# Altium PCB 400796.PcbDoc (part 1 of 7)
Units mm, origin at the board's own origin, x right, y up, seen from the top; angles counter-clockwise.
Board outline 53 x 53 mm, 6 copper layers (Top Layer, Mid Layer 1, Mid Layer 2, Mid Layer 3, Mid Layer 4, Bottom Layer), stack 1.494 mm thick; 319 components, 236 nets, 1249 pads, 2569 vias.
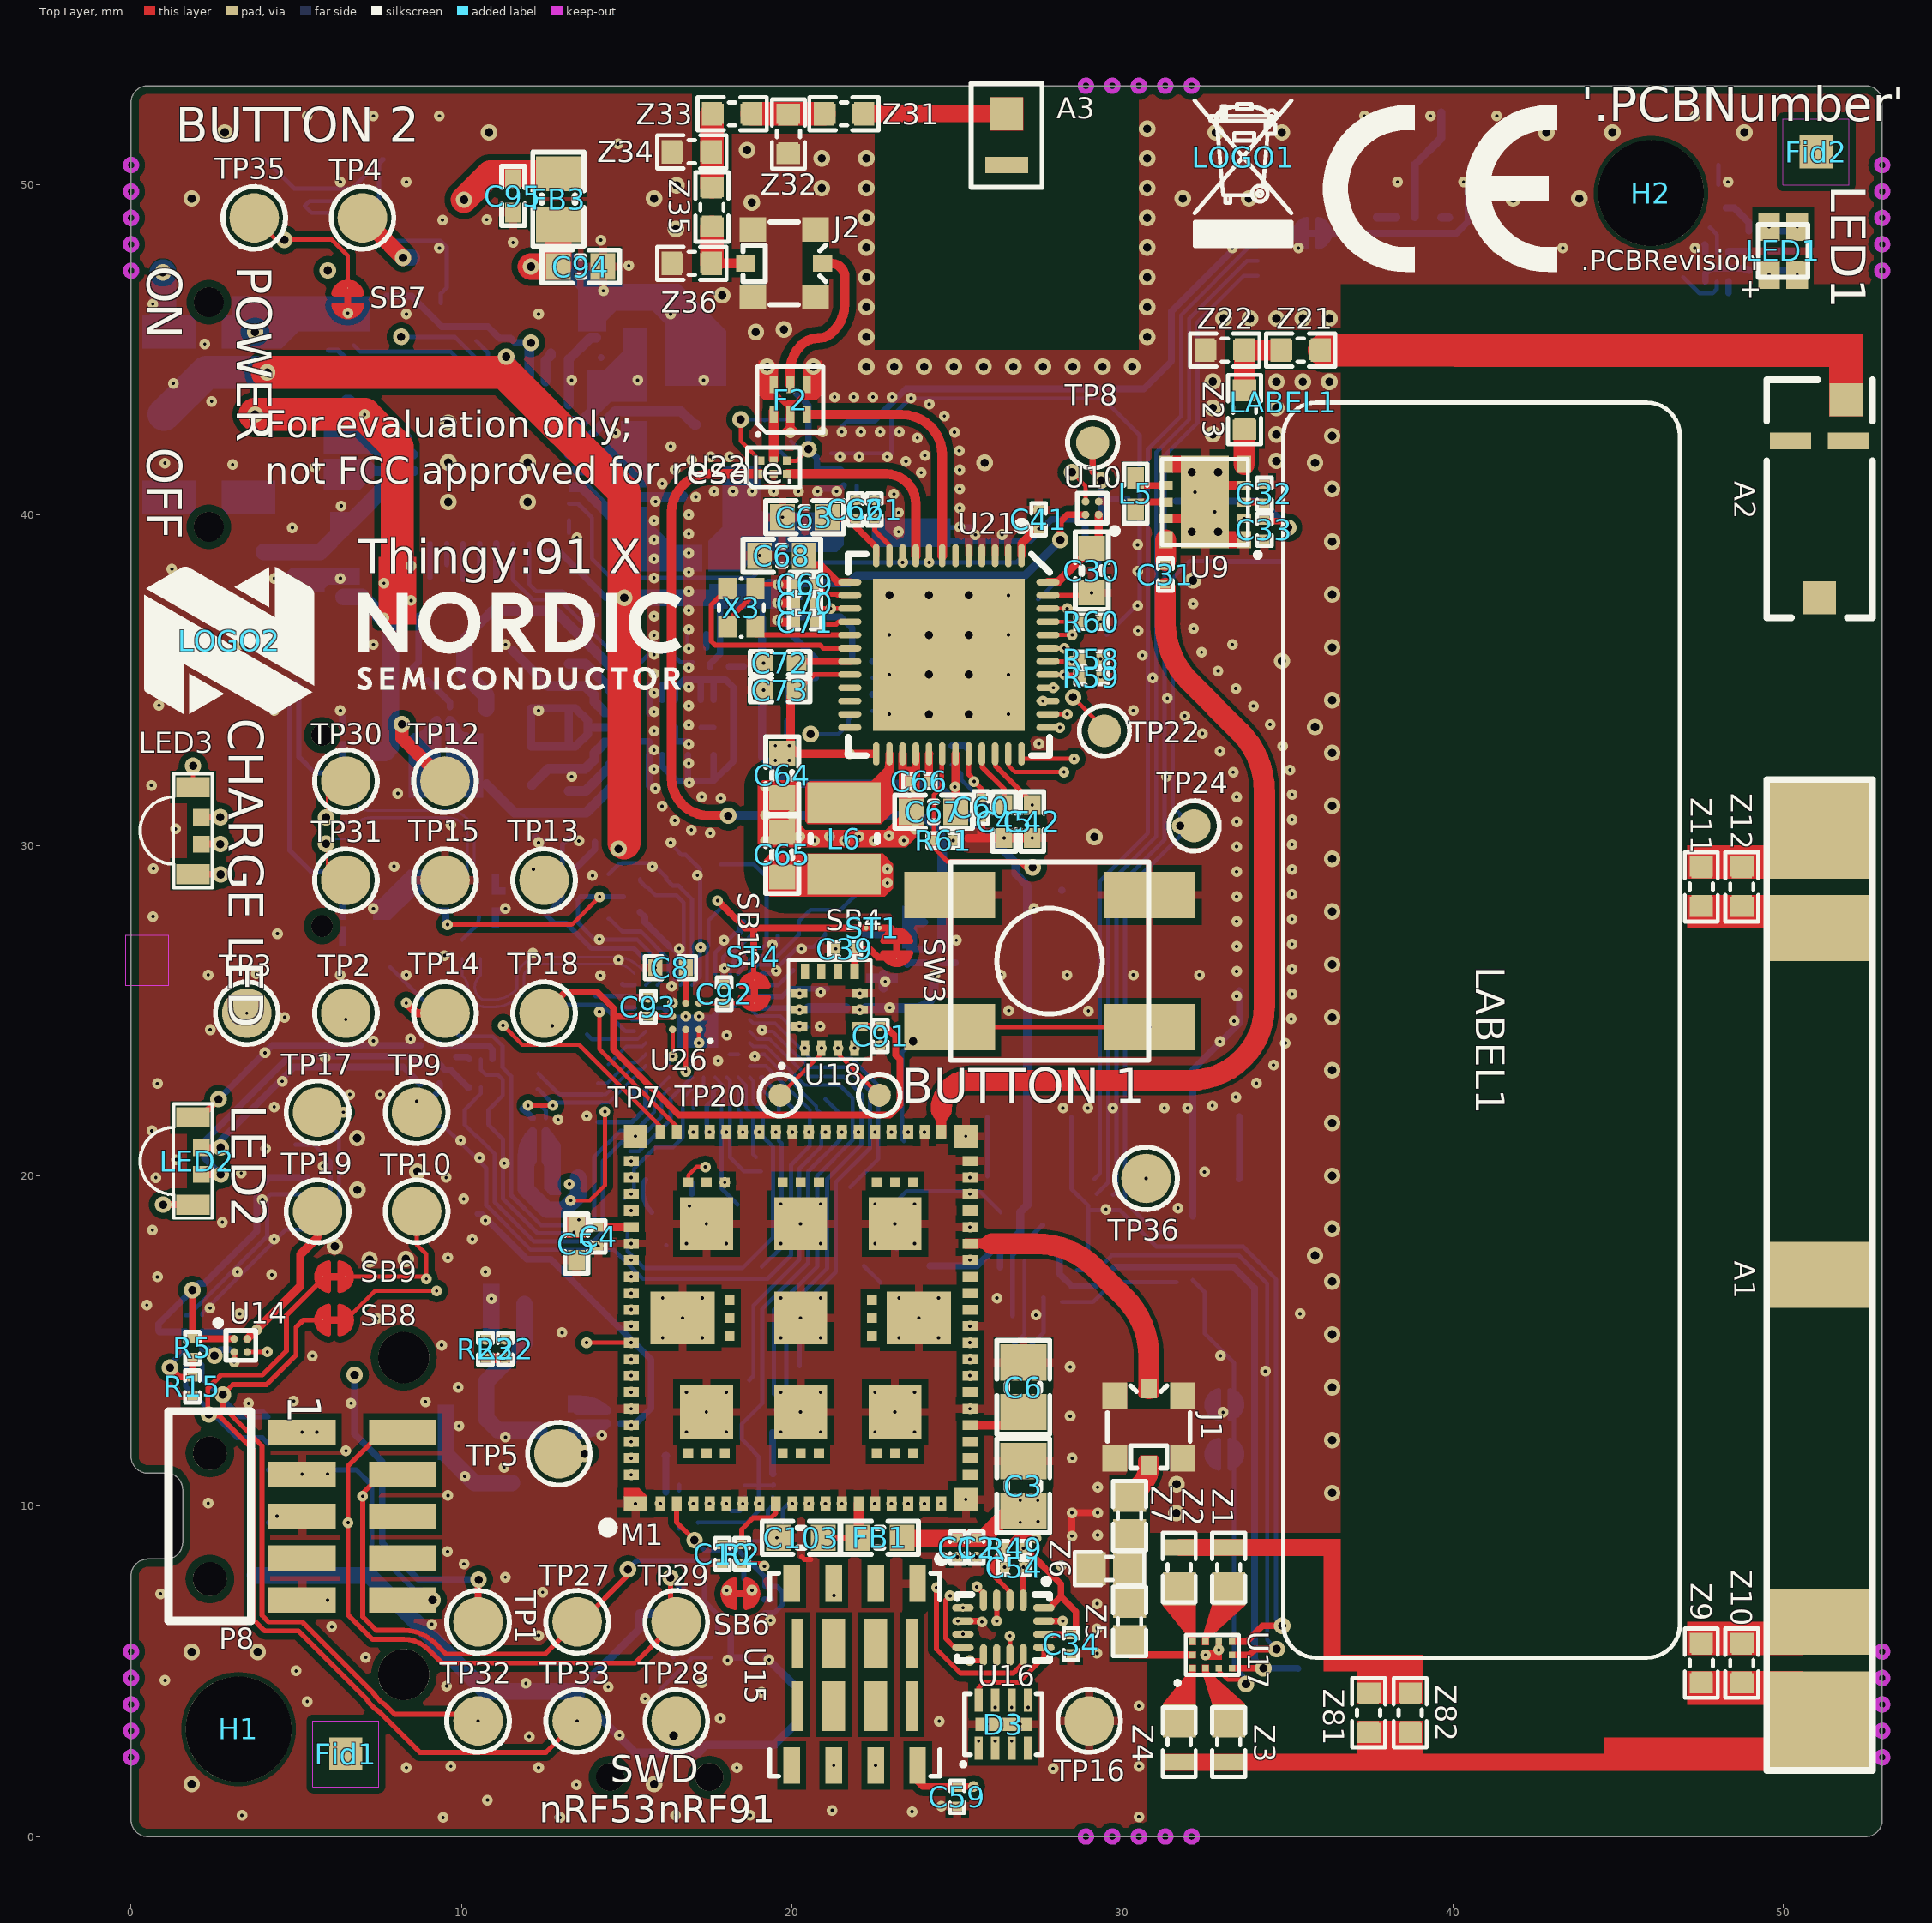
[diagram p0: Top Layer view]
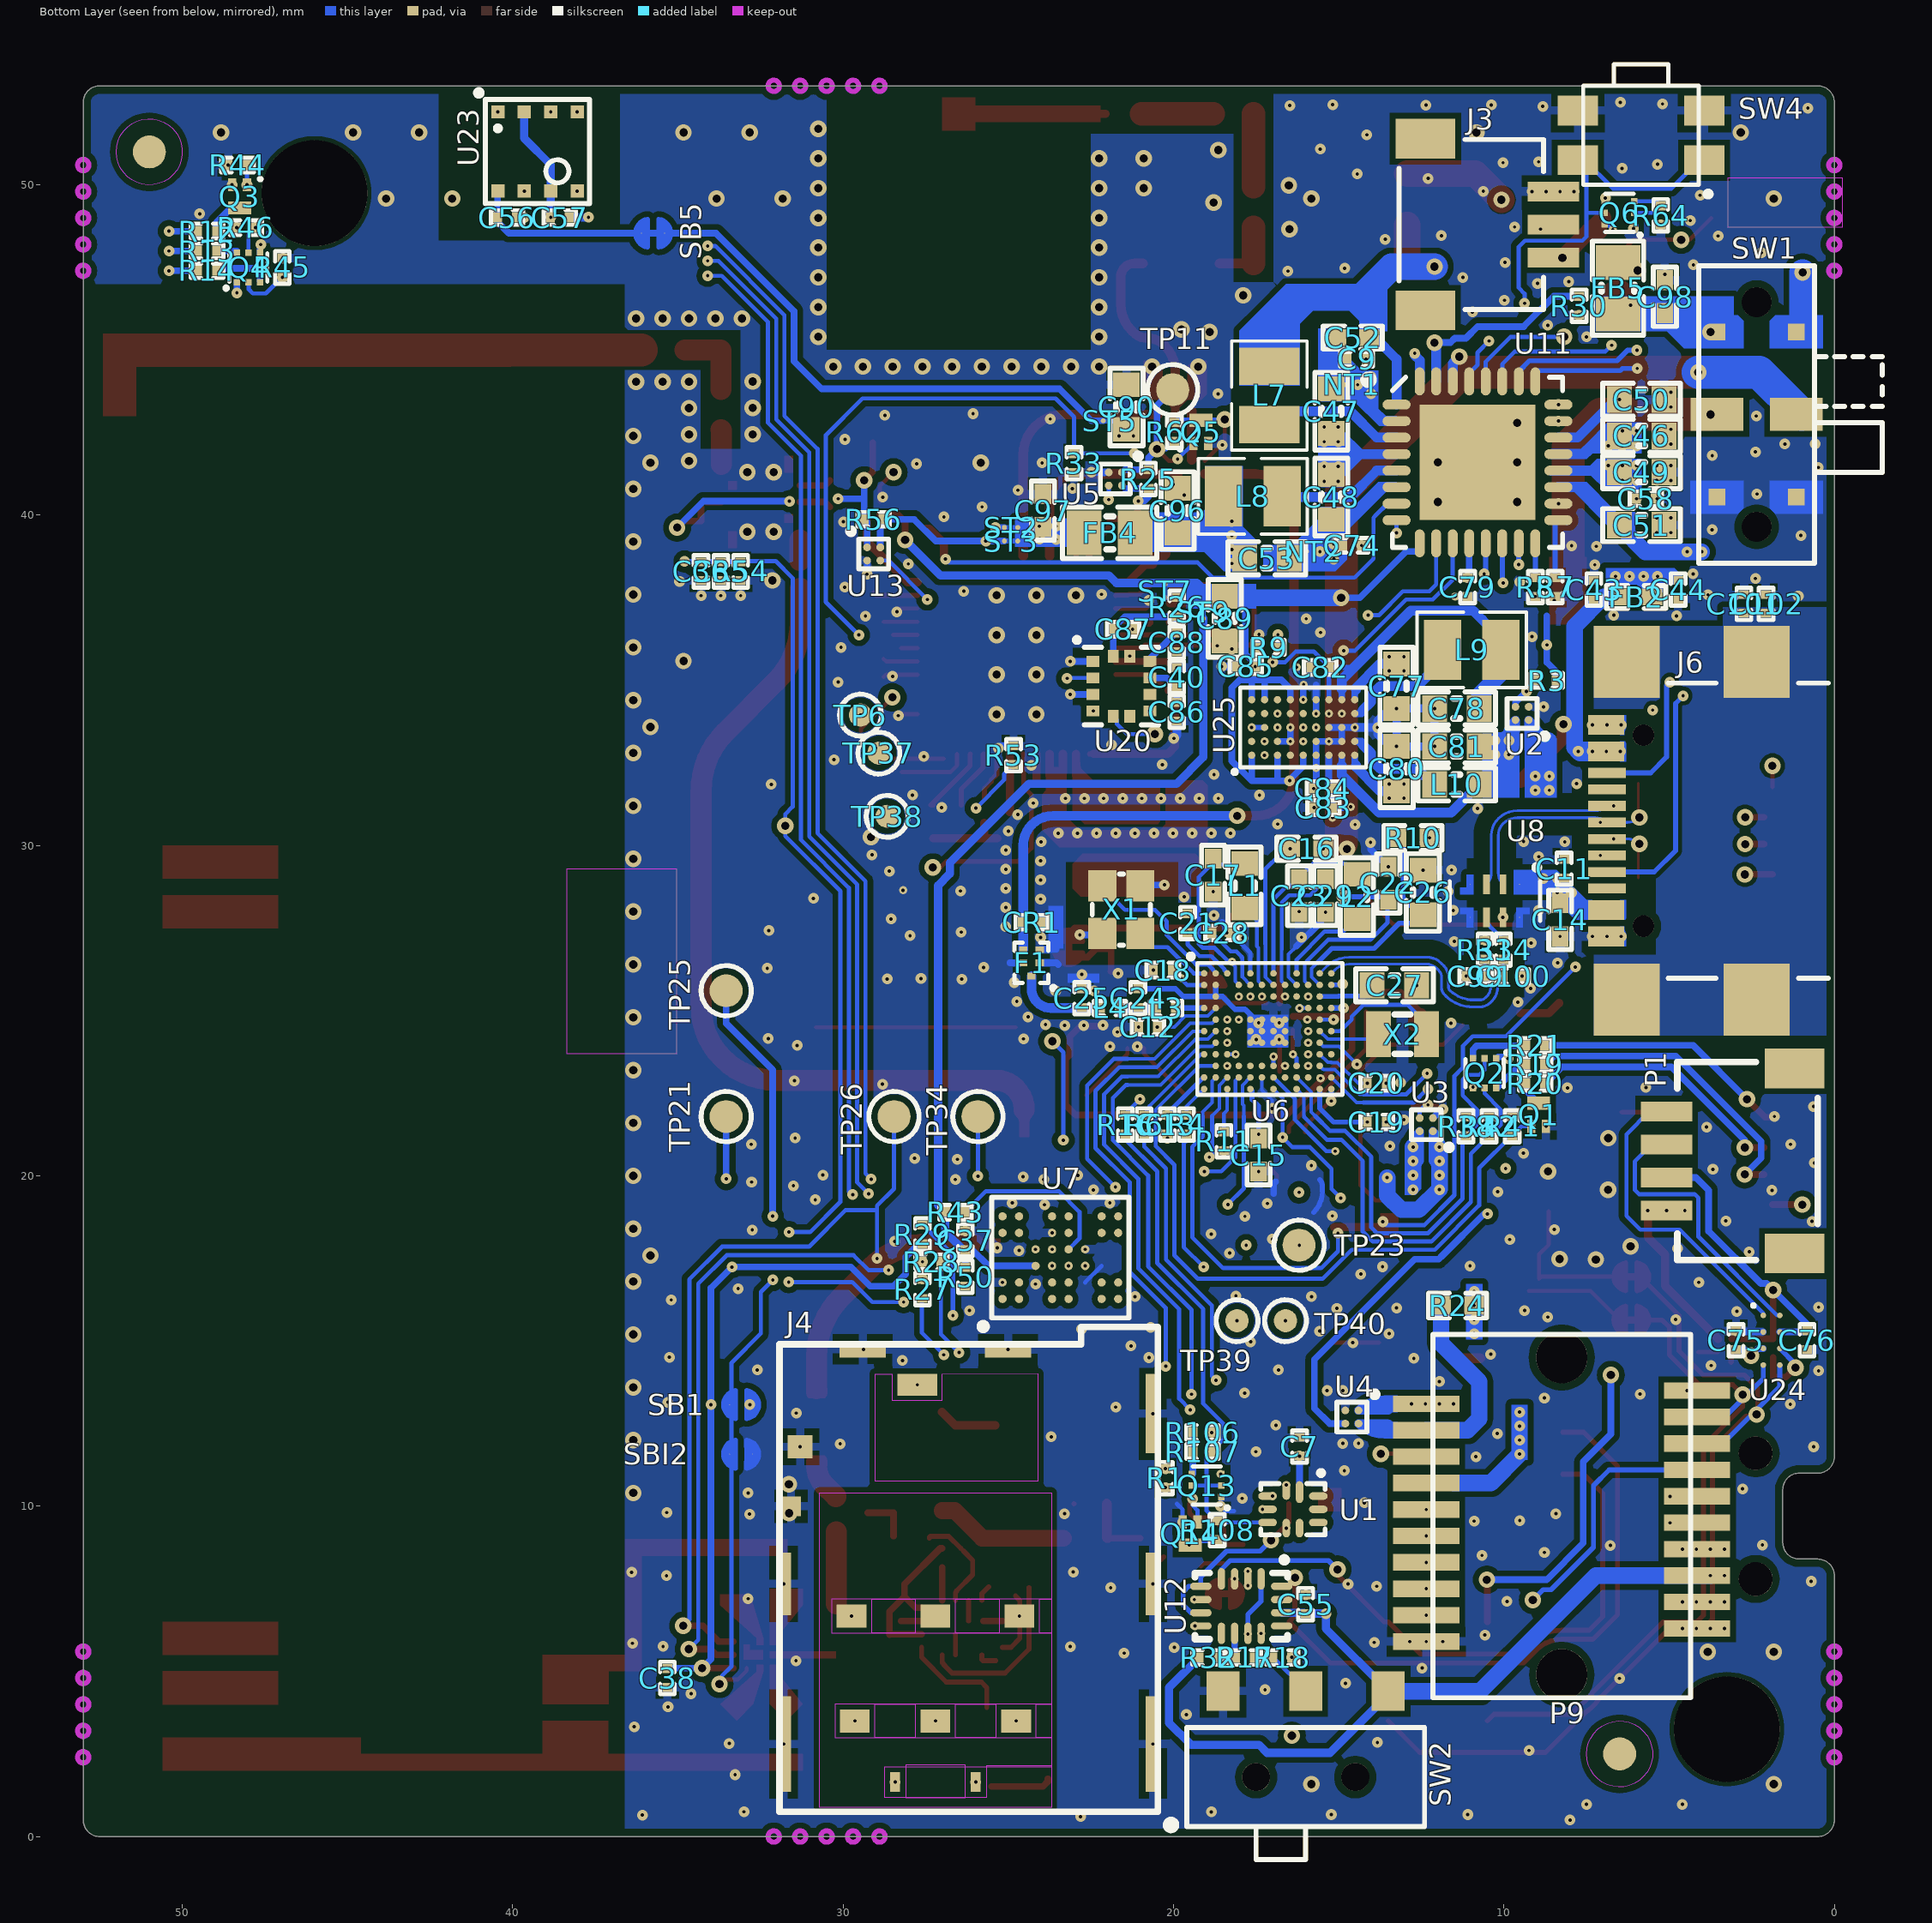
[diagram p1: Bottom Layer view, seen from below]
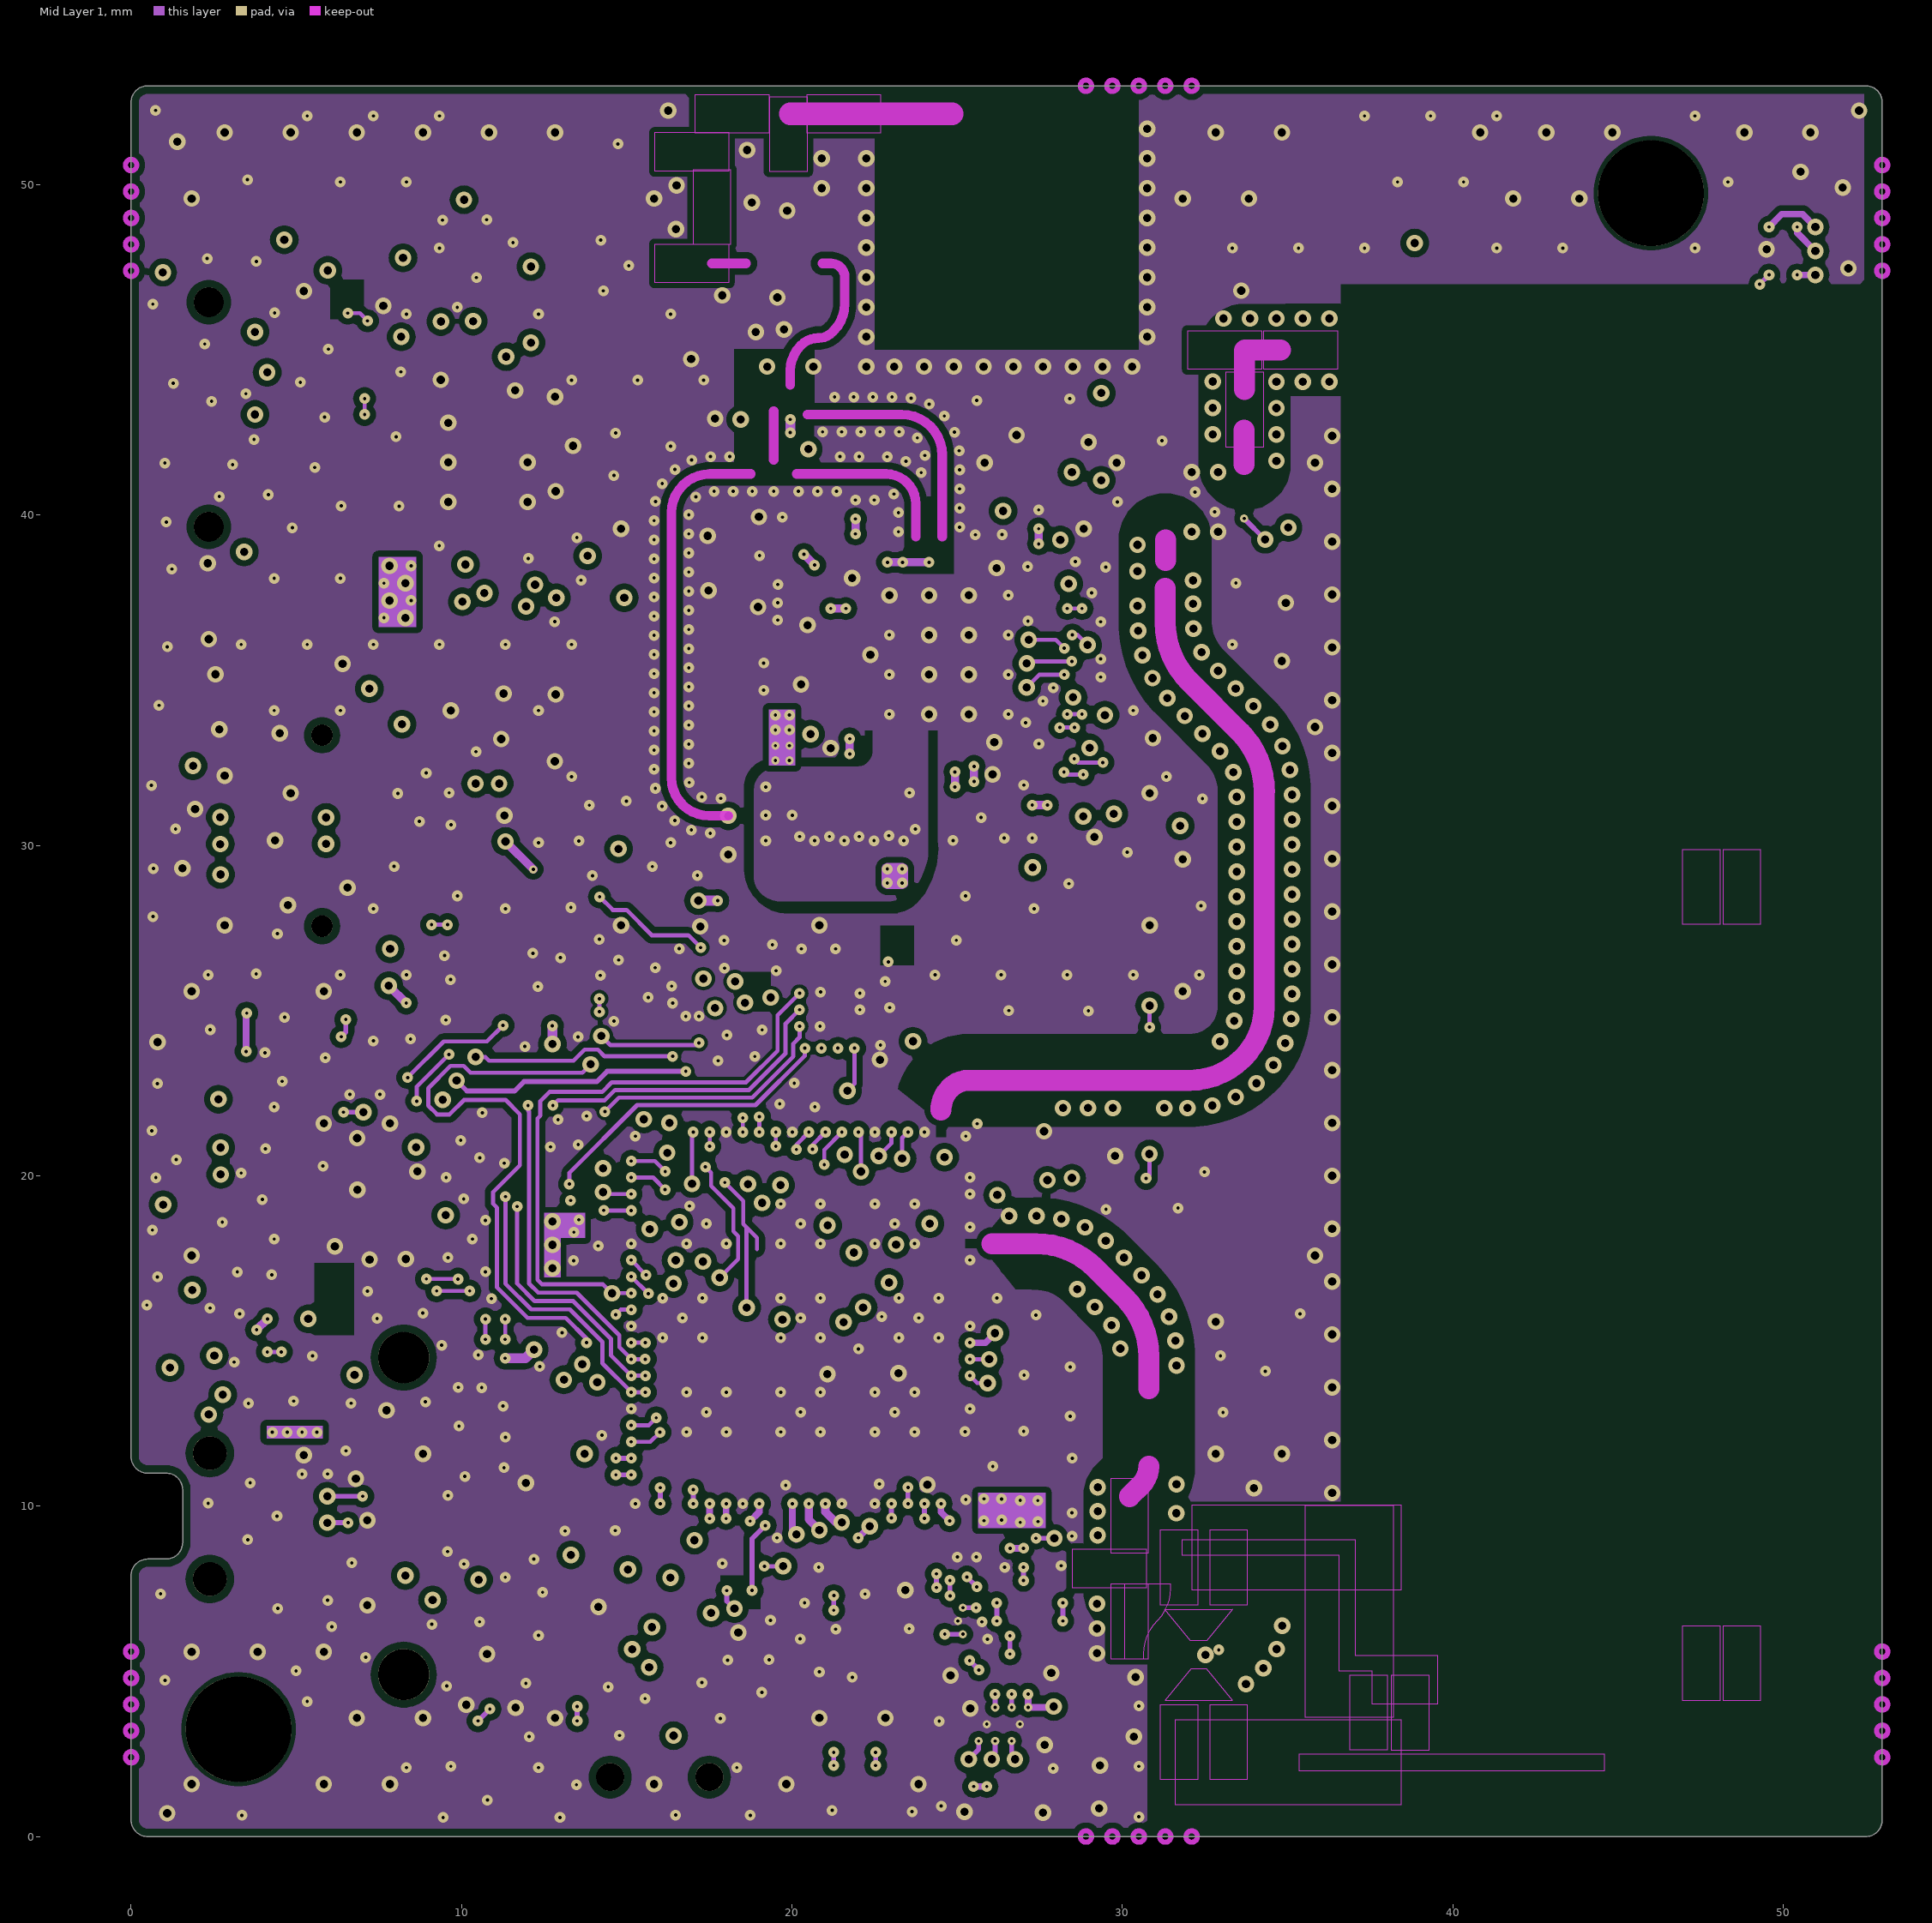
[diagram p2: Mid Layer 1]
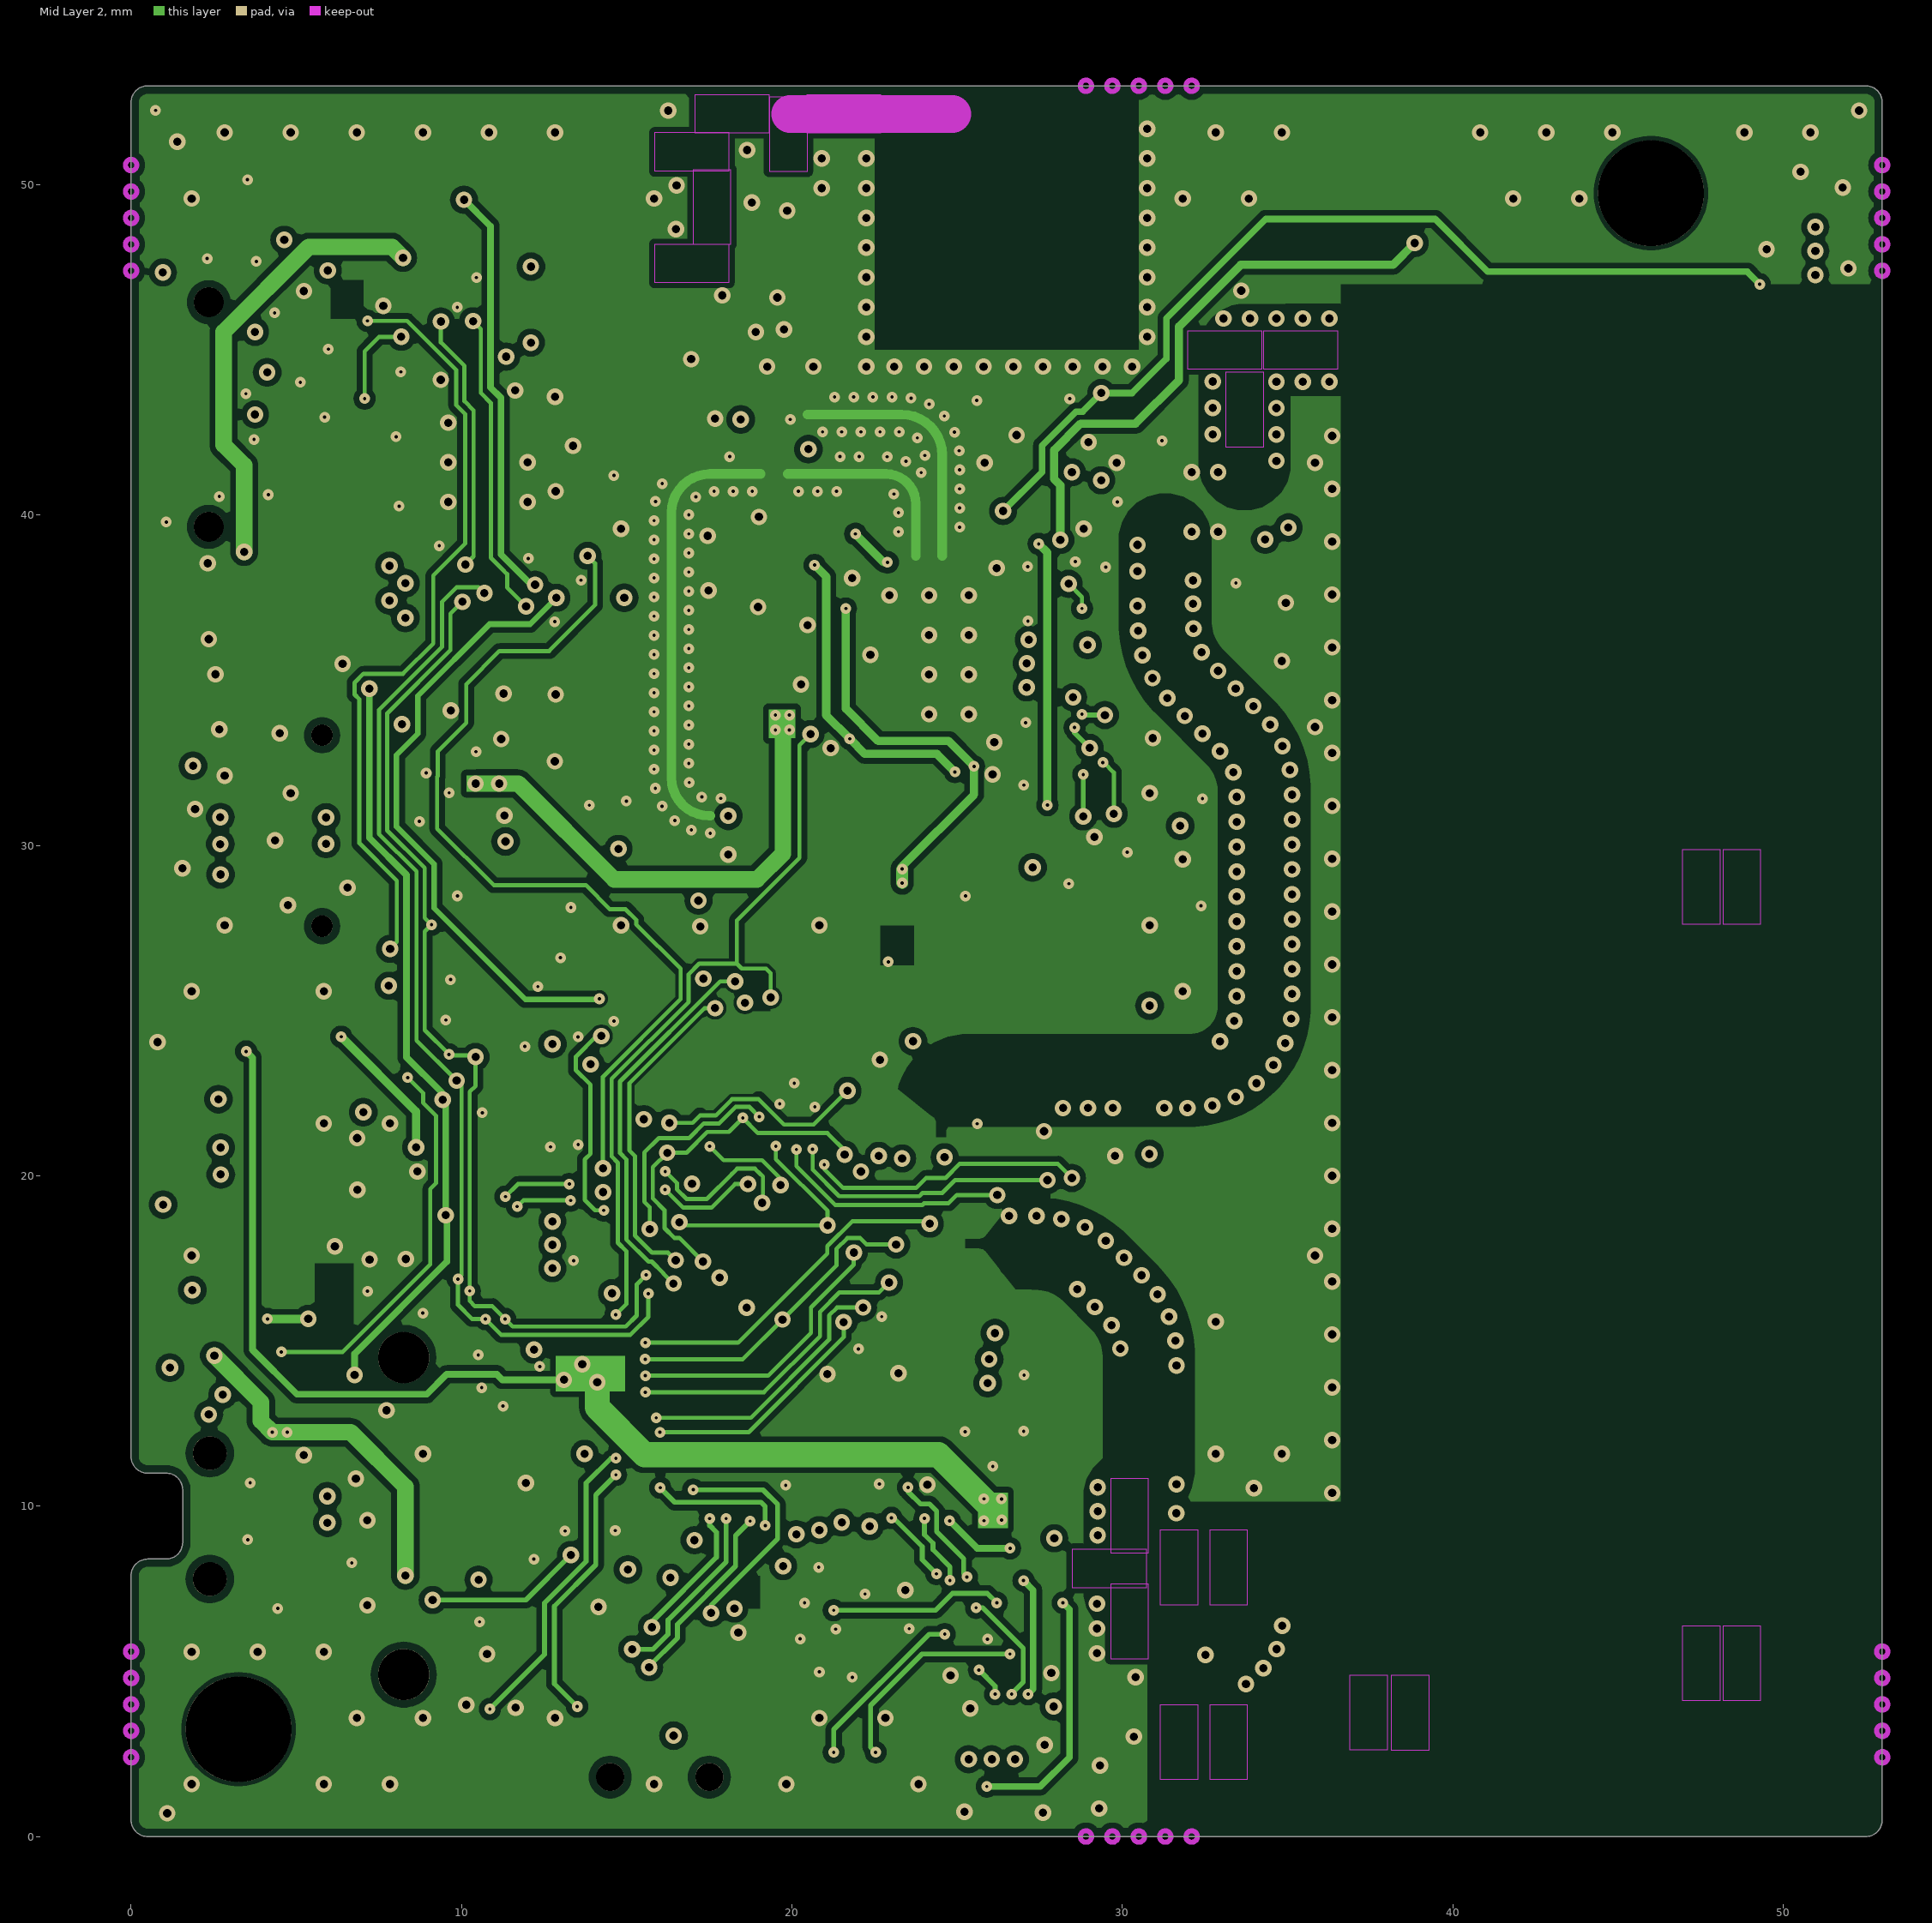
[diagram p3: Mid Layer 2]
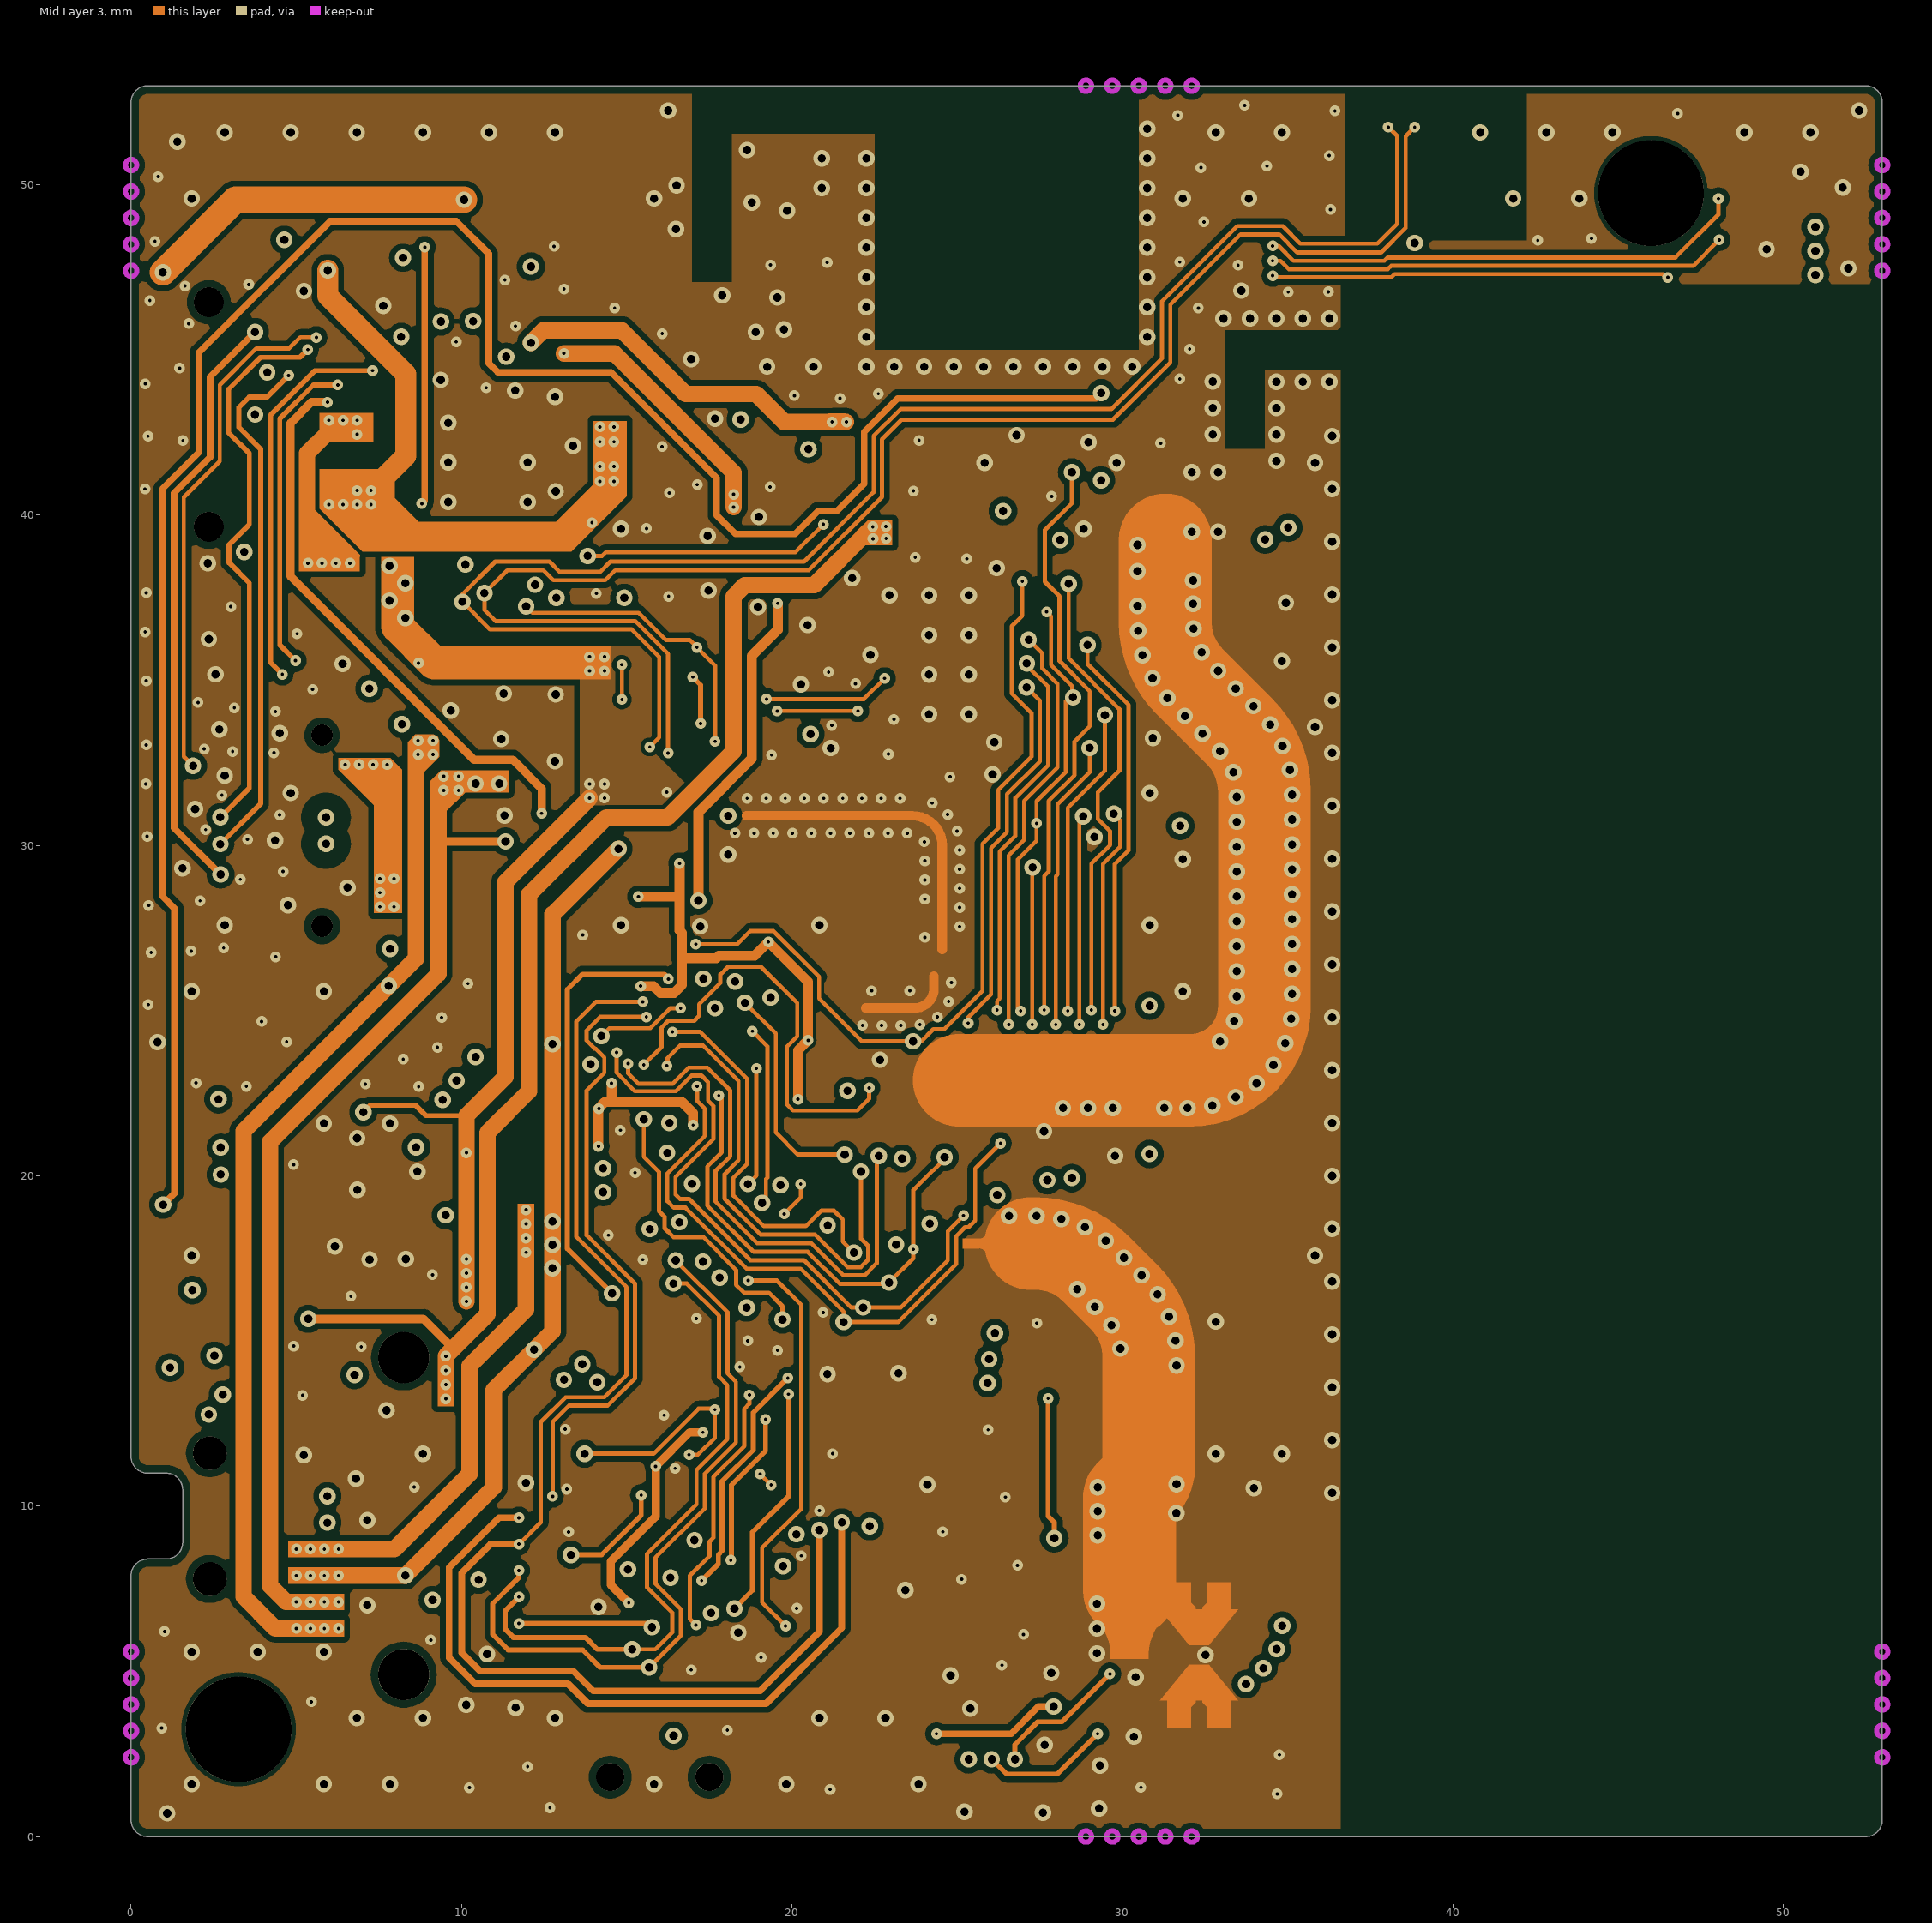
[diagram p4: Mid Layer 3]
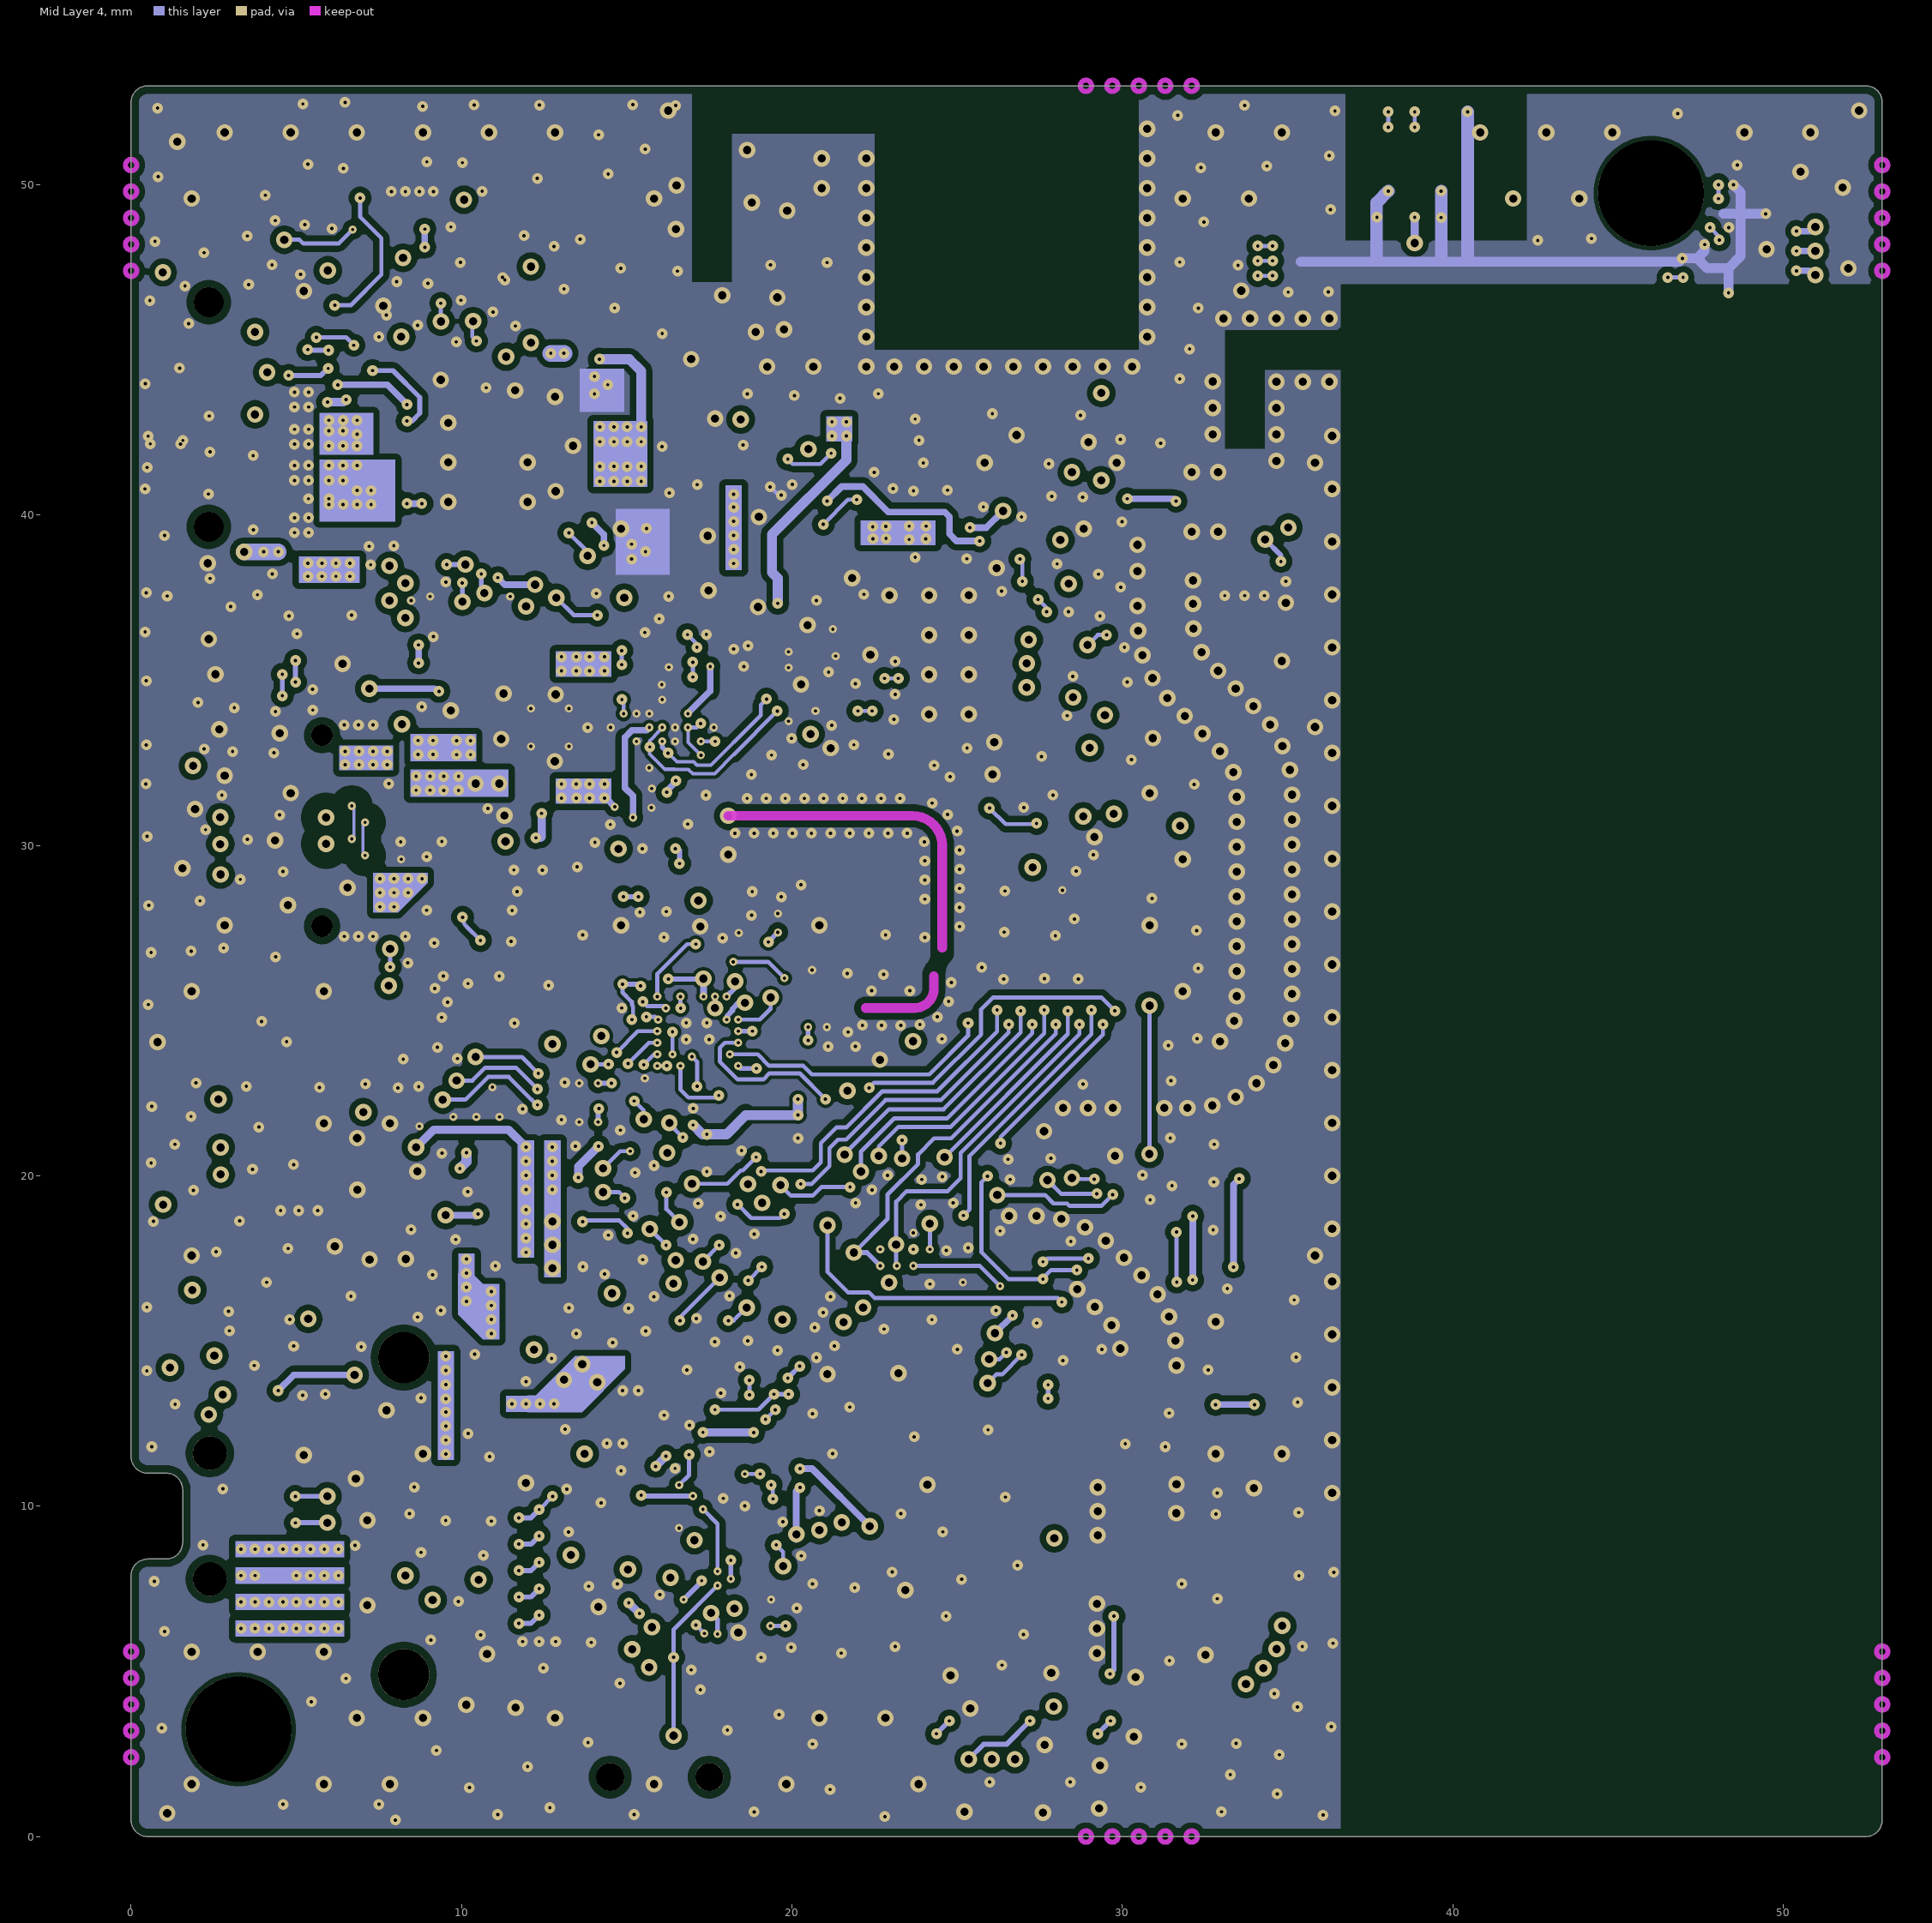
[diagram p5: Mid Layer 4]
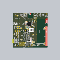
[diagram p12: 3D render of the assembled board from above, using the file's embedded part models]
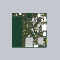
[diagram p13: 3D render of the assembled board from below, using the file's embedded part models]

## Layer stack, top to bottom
Top Solder: solder mask 0.05, Solder Resist Halogen-Free, Dk 3.5
Top Layer: signal copper 0.035
Dielectric1: prepreg 0.071, FR-4 Halogen-Free, Dk 4.2
Mid Layer 1: signal copper 0.035
Dielectric 3: prepreg 0.071, FR-4 Halogen-Free, Dk 4.2
Mid Layer 2: signal copper 0.035
Dielectric 2: core 1, Dk 4.51
Mid Layer 3: signal copper 0.035
Dielectric 1: prepreg 0.071, FR-4 Halogen-Free, Dk 4.2
Mid Layer 4: signal copper 0.035
Dielectric 4: prepreg 0.071, FR-4 Halogen-Free, Dk 4.2
Bottom Layer: signal copper 0.035
Bottom Solder: solder mask 0.05, Solder Resist Halogen-Free, Dk 3.5

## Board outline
0,0.5 ccw(c0.5,0.5) 0.5,0 52.5,0 ccw(c52.5,0.5) 53,0.5 53,52.5 ccw(c52.5,52.5) 52.5,53 0.5,53 ccw(c0.5,52.5) 0,52.5 0,11.5 ccw(c0.5,11.5) 0.5,11 1.06,11 cw(c1.06,10.5) 1.56,10.5 1.56,8.9 cw(c1.06,8.9) 1.06,8.4 0.5,8.4 ccw(c0.5,7.9) 0,7.9

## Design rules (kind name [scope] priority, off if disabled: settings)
BoardOutlineClearance BoardOutlineClearance_Power_SW [HasFootprint('Switch-Slide-RA-J-Lead-DPDT-8.5x3.5mm')] p1: gap=0.15 ignorepadtopadclearanceinfootprint=FALSE
BoardOutlineClearance [(OnLayer('Top Layer') or OnLayer('Bottom Layer') or OnLayer('Mid Layer 1') or OnLayer('Mid Layer 2') or OnLayer('Mid Layer 3') or OnLayer('Mid Layer 4')) and not Keepout] p2: gap=0.24 ignorepadtopadclearanceinfootprint=FALSE
Clearance Clearance_NPTH [InPadClass('NPTH')] p1: gap=0.127 ignorepadtopadclearanceinfootprint=FALSE
Clearance "Schematic Clearance Constraint_1" [InComponent('H2')] p2: gap=0.254 ignorepadtopadclearanceinfootprint=TRUE except(0: Arc-Hole Track-Hole SMDPad-Hole THPad-Hole Via-Hole Fill-Hole Poly-Hole Region-Hole Text-Hole)
Clearance "Schematic Clearance Constraint" [InComponent('H1')] p3: gap=0.254 ignorepadtopadclearanceinfootprint=TRUE except(0: Arc-Hole Track-Hole SMDPad-Hole THPad-Hole Via-Hole Fill-Hole Poly-Hole Region-Hole Text-Hole)
Clearance "Stitching GND blind" [IsStitchingVia and (InDrillLayerPair('Top Layer - Mid Layer 1') or InDrillLayerPair('Mid Layer 4 - Bottom Layer')) and InNet('GND') vs (IsVia and InDrillLayerPair('Top Layer - Bottom Layer')) Or IsPad] p4: gap=1 ignorepadtopadclearanceinfootprint=FALSE
Clearance "Stitching GND" [IsStitchingVia and InNet('GND') vs IsVia Or IsPad] p5: gap=0.25 ignorepadtopadclearanceinfootprint=FALSE
Clearance Clearance_nRF5340 [All vs WithinRoom('nRF53')] p6: gap=0.1 ignorepadtopadclearanceinfootprint=FALSE except(0.072: Arc-SMDPad Arc-Via Track-SMDPad Track-Via SMDPad-SMDPad SMDPad-Via THPad-Via Via-Via)
Clearance Clearance_nPM6001 [OnLayer('Mid Layer 4') vs WithinRoom('nPM6001')] p7: gap=0.105 ignorepadtopadclearanceinfootprint=FALSE
Clearance USB_Poly_Clearance [(InNamedPolygon('Top Layer-GND')) or (InNamedPolygon('Mid_Layer_1_Codec-GND')) or (InNamedPolygon('Mid_Layer_3-GND')) or (InNamedPolygon('Mid_Layer_3-GND')) or (InNamedPolygon('Mid_Layer_4-GND')) or (InNamedPolygon('Mid_Layer_1-AGND') or InNamedPolygon('Bottom_Layer-GND')) vs InAnyDifferentialPair] p8: gap=0.5 ignorepadtopadclearanceinfootprint=FALSE
Clearance "Diff_Pair_Clearance_Other _Diffpair" [InAnyDifferentialPair and (IsArc or IsTrack)] p9: gap=0.3 ignorepadtopadclearanceinfootprint=FALSE
Clearance Diff_Pair_Clearance_Not_Diffpair [InAnyDifferentialPair and (IsArc or IsTrack) vs not InAnyDifferentialPair] p10: gap=0.125 ignorepadtopadclearanceinfootprint=FALSE
Clearance Microvia_Clearance [AsMM(ViaDiameter) = 0.3 vs AsMM(ViaDiameter) = 0.3] p11: gap=0.1 ignorepadtopadclearanceinfootprint=FALSE
Clearance "NPTH clearance_MIC" [(Not PadIsPlated And HoleSize > 0) and (InRegionRelative(100,1032,150,1092) or InRegionRelative(1000,1952,1050,2002))] p12: gap=0.1 ignorepadtopadclearanceinfootprint=FALSE
Clearance "NPTH clearance" [Not PadIsPlated And HoleSize > 0] p13: gap=0.22 ignorepadtopadclearanceinfootprint=FALSE
Clearance RF_Clerance [InNetClass('RF')] p14: gap=0.125 ignorepadtopadclearanceinfootprint=FALSE
Clearance RF_Clerance_RF_BLE/WIFI [InNetClass('RF_BLE/WIFI') vs InNamedPolygon('Top_Layer-GND') or InNamedPolygon('Bottom_Layer-GND')] p15: gap=0.2 ignorepadtopadclearanceinfootprint=FALSE
Clearance Polygon_Clearance_Codec [InNamedPolygon('Mid_Layer_1_Codec-GND')] p16: gap=0.125 ignorepadtopadclearanceinfootprint=FALSE
Clearance Polygon_Clearance [(InNamedPolygon('Top_Layer-GND')) or (InNamedPolygon('Mid_Layer_1-GND')) or (InNamedPolygon('Mid_Layer_2-GND')) or (InNamedPolygon('Mid_Layer_3-GND')) or (InNamedPolygon('Mid_Layer_4-GND')) or (InNamedPolygon('Mid_Layer_4-AGND') or InNamedPolygon('Bottom_Layer-GND'))] p17: gap=0.18 ignorepadtopadclearanceinfootprint=FALSE
Clearance [All] p18: gap=0.125 ignorepadtopadclearanceinfootprint=FALSE
ComponentClearance [All] p1 off: gap=0.254 collisioncheckmode=3 verticalgap=0.254 showdistances=FALSE
DiffPairsRouting [InAnyDifferentialPair] p1: maxlimit=0.127 minlimit=0.127 mostfreqgap=0.127 toplayer_minwidth=0.083 toplayer_maxwidth=0.083 toplayer_prefwidth=0.083 midlayer1_minwidth=0.041 midlayer1_maxwidth=0.041 midlayer1_prefwidth=0.041 midlayer2_minwidth=0.059 midlayer2_maxwidth=0.059 midlayer2_prefwidth=0.059 midlayer3_minwidth=0.059 midlayer3_maxwidth=0.059 midlayer3_prefwidth=0.059 midlayer4_minwidth=0.041 midlayer4_maxwidth=0.041 midlayer4_prefwidth=0.041 bottomlayer_minwidth=0.083 bottomlayer_maxwidth=0.083 bottomlayer_prefwidth=0.083 impedanceprofiledriven=TRUE impedanceprofileid={B73BED5C-2360-4F1A-9E9C-C8917F192C1F} impedanceprofilevalue=90.000000 maxuncoupledlength=12.7
FabricationTestPointUsage TestPointUsage [All] p1: valid=0 allowmultiple=FALSE
FabricationTestpoint Testpoint [All] p1: side=3 testpointundercomponent=TRUE minsize=1.016 maxsize=2.54 preferedsize=1.524 minholesize=0 maxholesize=1.016 preferedholesize=0.813 testpointgrid=0.025 allowsidetop=TRUE allowsidebottom=TRUE usegrid=TRUE gridtolerance=0
Height [All] p1 off: minheight=0 maxheight=25.4 prefheight=12.7
HoleSize HoleSize_Laser_Via [IsVia and (InDrillLayerPair('Top Layer - Mid Layer 1') or InDrillLayerPair('Mid Layer 1 - Mid Layer 2') or InDrillLayerPair('Mid Layer 3 - Mid-Layer 4') or InDrillLayerPair('Mid Layer 4 - Bottom Layer'))] p1: absolutevalues=TRUE maxlimit=0.1 minlimit=0.1 maxpercent=80.000 minpercent=20.000
HoleSize HoleSize_Mech_Via [IsVia and (InDrillLayerPair('Top Layer - Bottom Layer') or InDrillLayerPair('Mid Layer 1 - Mid Layer 4'))] p2: absolutevalues=TRUE maxlimit=0.25 minlimit=0.25 maxpercent=80.000 minpercent=20.000
HoleSize [All] p3: absolutevalues=TRUE maxlimit=5 minlimit=0.1 maxpercent=80.000 minpercent=20.000
HoleToHoleClearance HoleToHoleClearance_PMIC [InDrillLayerPair('Mid Layer 4 - Bottom Layer') and InRegionRelative(580,1280,700,1350) vs InDrillLayerPair('Mid Layer 4 - Bottom Layer') and InRegionRelative(580,1280,700,1350)] p1: gap=0.29 allowstackedmicrovias=FALSE
HoleToHoleClearance HoleToHoleClearance_T-B_T-B [InDrillLayerPair('Top Layer - Bottom Layer') vs InDrillLayerPair('Top Layer - Bottom Layer')] p2 off: gap=0.45 allowstackedmicrovias=FALSE
HoleToHoleClearance HoleToHoleClearance_TH-TH [AsMM(ViaDiameter) = 0.50 vs AsMM(ViaDiameter) = 0.50] p3: gap=0.45 allowstackedmicrovias=FALSE
HoleToHoleClearance HoleToHoleClearance_TH-Micro [AsMM(ViaDiameter) = 0.50 vs AsMM(ViaDiameter) = 0.30] p4: gap=0.45 allowstackedmicrovias=FALSE
HoleToHoleClearance HoleToHoleClearance_Micro-Micro [AsMM(ViaDiameter) = 0.32 vs AsMM(ViaDiameter) = 0.32] p5: gap=0.3 allowstackedmicrovias=FALSE
HoleToHoleClearance HoleToHoleClearance_T-B_M1-M4 [InDrillLayerPair('Top Layer - Bottom Layer') vs InDrillLayerPair('Mid Layer 1 - Mid Layer 4')] p6 off: gap=0.45 allowstackedmicrovias=FALSE
HoleToHoleClearance HoleToHoleClearance_T-B_T-M1 [InDrillLayerPair('Top Layer - Bottom Layer') vs InDrillLayerPair('Top Layer - Mid Layer 1')] p7 off: gap=0.33 allowstackedmicrovias=FALSE
HoleToHoleClearance HoleToHoleClearance_T-B_M1-M2 [InDrillLayerPair('Top Layer - Bottom Layer') vs InDrillLayerPair('Mid Layer 1 - Mid Layer 2')] p8 off: gap=0.33 allowstackedmicrovias=FALSE
HoleToHoleClearance HoleToHoleClearance_T-B_M3-M4 [InDrillLayerPair('Top Layer - Bottom Layer') vs InDrillLayerPair('Mid Layer 3 - Mid Layer 4')] p9 off: gap=0.33 allowstackedmicrovias=FALSE
HoleToHoleClearance HoleToHoleClearance_T-B_M4-B [InDrillLayerPair('Top Layer - Bottom Layer') vs InDrillLayerPair('Mid Layer 4 - Bottom Layer')] p10 off: gap=0.33 allowstackedmicrovias=FALSE
HoleToHoleClearance HoleToHoleClearance_M1-M4_M1-M4 [InDrillLayerPair('Mid Layer 1 - Mid Layer 4') vs InDrillLayerPair('Mid Layer 1 - Mid Layer 4')] p11 off: gap=0.45 allowstackedmicrovias=FALSE
HoleToHoleClearance HoleToHoleClearance_M1-M4_T-M1-Shield [InDrillLayerPair('Mid Layer 1 - Mid Layer 4') and IsShieldingVia vs InDrillLayerPair('Top Layer - Mid Layer 1')] p12 off: gap=0 allowstackedmicrovias=TRUE
HoleToHoleClearance HoleToHoleClearance_T-M1-M1-M2-Shield [InDrillLayerPair('Top Layer - Mid Layer 1') and IsShieldingVia vs InDrillLayerPair('Mid Layer 1 - Mid Layer 2')] p13 off: gap=0 allowstackedmicrovias=TRUE
HoleToHoleClearance "HoleToHoleClearance_M1-M4_T-M1-Shield Manual" [InDrillLayerPair('Mid Layer 1 - Mid Layer 4') and (InRegionRelative(1100,200,1310,600) or InRegionRelative(1187,1493,1212,1553)) vs InDrillLayerPair('Top Layer - Mid Layer 1')] p14 off: gap=0 allowstackedmicrovias=TRUE
HoleToHoleClearance HoleToHoleClearance_M1-M4_T-M1 [InDrillLayerPair('Mid Layer 1 - Mid Layer 4') vs InDrillLayerPair('Top Layer - Mid Layer 1')] p15 off: gap=0.375 allowstackedmicrovias=FALSE
HoleToHoleClearance HoleToHoleClearance_M1-M4_M1-M2 [InDrillLayerPair('Mid Layer 1 - Mid Layer 4') vs InDrillLayerPair('Mid Layer 1 - Mid Layer 2')] p16 off: gap=0.375 allowstackedmicrovias=FALSE
HoleToHoleClearance HoleToHoleClearance_M1-M4_M3-M4 [InDrillLayerPair('Mid Layer 1 - Mid Layer 4') vs InDrillLayerPair('Mid Layer 3 - Mid Layer 4')] p17 off: gap=0.375 allowstackedmicrovias=FALSE
HoleToHoleClearance HoleToHoleClearance_M1-M4_M4-B [InDrillLayerPair('Mid Layer 1 - Mid Layer 4') vs InDrillLayerPair('Mid Layer 4 - Bottom Layer')] p18 off: gap=0.375 allowstackedmicrovias=FALSE
HoleToHoleClearance HoleToHoleClearance_T-M1_T-M1 [InDrillLayerPair('Top Layer - Mid Layer 1') vs InDrillLayerPair('Top Layer - Mid Layer 1')] p19 off: gap=0.3 allowstackedmicrovias=FALSE
HoleToHoleClearance HoleToHoleClearance_T-M1_M1-M2 [InDrillLayerPair('Top Layer - Mid Layer 1') vs InDrillLayerPair('Mid Layer 1 - Mid Layer 2')] p20 off: gap=0.3 allowstackedmicrovias=FALSE
HoleToHoleClearance HoleToHoleClearance_M1-M2_M1-M2 [InDrillLayerPair('Mid Layer 1 - Mid Layer 2') vs InDrillLayerPair('Mid Layer 1 - Mid Layer 2')] p21 off: gap=0.325 allowstackedmicrovias=FALSE
HoleToHoleClearance HoleToHoleClearance_M3-M4_M3-M4 [InDrillLayerPair('Mid Layer 3 - Mid Layer 4') vs InDrillLayerPair('Mid Layer 3 - Mid Layer 4')] p22 off: gap=0.325 allowstackedmicrovias=TRUE
HoleToHoleClearance HoleToHoleClearance_M3-M4_M4-B [InDrillLayerPair('Mid Layer 3 - Mid Layer 4') vs InDrillLayerPair('Mid Layer 4 - Bottom Layer')] p23 off: gap=0.3 allowstackedmicrovias=TRUE
HoleToHoleClearance HoleToHoleClearance_M4-B_M4-B_nRF53 [WithinRoom('nRF53') and InDrillLayerPair('Mid Layer 4 - Bottom Layer') vs WithinRoom('nRF53') and InDrillLayerPair('Mid Layer 4 - Bottom Layer')] p24 off: gap=0.22 allowstackedmicrovias=FALSE
HoleToHoleClearance HoleToHoleClearance_M4-B_M4-B [InDrillLayerPair('Mid Layer 4 - Bottom Layer') vs InDrillLayerPair('Mid Layer 4 - Bottom Layer')] p25 off: gap=0.325 allowstackedmicrovias=FALSE
MinimumAnnularRing [All] p1 off: minimumring=0.152
MinimumSolderMaskSliver MinimumSolderMaskSliver_exception [HasFootprint('SOTFL35P100X50-6N') or HasFootprint('DX07S016JA1R1500') or HasFootprint('DFN40P130X120X40-6N') or HasFootprint('BGA4C40P2X2_76X76X62') or HasFootprint('VM3011') or HasFootprint('WE-TPC_4848') or HasFootprint('BGA12C40P3X4_139X164X40') or HasFootprint('X2-DFN40P120X120X40_HS-7L') or HasFootprint('BGA45C40P5X9_217X364X49') or HasFootprint('SON50P210X160X65_HS-9N') or HasFootprint('BGA95C35P12X11_439X399X49')] p1: minsoldermaskwidth=0.05
MinimumSolderMaskSliver MinimumSolderMaskSliver_exception_1 [HasFootprint('TSQFP50P1600X1600X160-100N') or HasFootprint('BGA12C40P3X4_139X164X40') or HasFootprint('SAFFB2G45MA0F0A')] p2: minsoldermaskwidth=0.06
MinimumSolderMaskSliver [All] p3: minsoldermaskwidth=0.099
NetAntennae NetAntennae_allowed [InNet('ANT') or InNet('PVSS1') or InNet('PVSS2')] p1: netantennaetolerance=40
NetAntennae [All] p2: netantennaetolerance=0
PolygonConnect PolygonConnect_1 [isVia or HasFootprint('COAXIAL-SWF') or HasFootprint('2 PIN STARPOINT') or HasFootprint('C1608X06L-C1005X04M') or HasFootprint('UFDFN50P120X250X55-8N') or InNet('Shield')] p1: connectstyle=Direct reliefconductorwidth=0.254 reliefentries=4 polygonreliefangle="90 Angle" airgapwidth=0.254
PolygonConnect [All] p2: connectstyle=Relief reliefconductorwidth=0.254 reliefentries=4 polygonreliefangle="90 Angle" airgapwidth=0.2
RoomDefinition nPM6001 [InComponentClass('nPM6001')] p1 off: confinementstyle=ConfineIn formatcopy=TRUE lockcomponents=FALSE outline 13.822,32.101 18.237,32.101 18.237,35.044 13.822,35.044
RoomDefinition nRF53 [InComponentClass('nRF53')] p2 off: confinementstyle=ConfineIn formatcopy=TRUE lockcomponents=FALSE outline 14.148,21.819 21.387,21.819 21.387,27.215 14.148,27.215
RoutingVias "Schematic Routing Via Style_1" [InComponent('H2')] p1: holewidth=0 width=0 viastyle="Through Hole" minholewidth=0 minwidth=0 maxholewidth=2 maxwidth=2
RoutingVias "Schematic Routing Via Style" [InComponent('H1')] p2: holewidth=0 width=0 viastyle="Through Hole" minholewidth=0 minwidth=0 maxholewidth=2 maxwidth=2
RoutingVias RoutingVias_Buried_Laser [InDrillLayerPair('Mid Layer 1 - Mid Layer 2') or InDrillLayerPair('Mid Layer 3 - Mid Layer 4')] p3: holewidth=0.1 width=0.325 viastyle="Through Hole" minholewidth=0.1 minwidth=0.325 maxholewidth=0.1 maxwidth=0.325 useviatemplates=TRUE viatemplateguid#1={9ABB6B76-5394-44E6-A882-B3597929173E} viatemplatename#1=v32h10m0mx0
RoutingVias RoutingVias_Buried_Mech [InDrillLayerPair('Mid Layer 1 - Mid Layer 4')] p4: holewidth=0.25 width=0.5 viastyle="Through Hole" minholewidth=0.25 minwidth=0.5 maxholewidth=0.25 maxwidth=0.5 useviatemplates=TRUE viatemplateguid#1={8EF9FDDC-A461-4832-97D7-10F555954D9C} viatemplatename#1=v50h25
RoutingVias RoutingVias_TH [InDrillLayerPair('Top Layer - Bottom Layer')] p5: holewidth=0.25 width=0.5 viastyle="Through Hole" minholewidth=0.25 minwidth=0.5 maxholewidth=0.25 maxwidth=0.5 useviatemplates=TRUE viatemplateguid#1={8EF9FDDC-A461-4832-97D7-10F555954D9C} viatemplatename#1=v50h25
RoutingVias RoutingVias_Blind_Laser [InDrillLayerPair('Top Layer - Mid Layer 1') or InDrillLayerPair('Mid Layer 4 - Bottom Layer')] p6: holewidth=0.1 width=0.325 viastyle="Through Hole" minholewidth=0.1 minwidth=0.25 maxholewidth=0.1 maxwidth=0.325 useviatemplates=TRUE viatemplateguid#1={1F3E73C2-C6A8-4428-A676-A14C7D9AFDCB} viatemplateguid#2={9ABB6B76-5394-44E6-A882-B3597929173E} viatemplatename#1=v25h10m0mx0 viatemplatename#2=v32h10m0mx0
ShortCircuit ShortCircuit_PVSS [InNet('PVSS1') or InNet('PVSS2') vs InNet('GND')] p1: allowed=TRUE
ShortCircuit [All] p2: allowed=FALSE
SilkToSolderMaskClearance SilkscreenOverComponentPads [IsPad] p1: minsilkscreentomaskgap=0.254 clearancetoexposedcopper=TRUE
SolderMaskExpansion SolderMaskExpansion_1 [IsVia] p1: expansion=0.102 istentingtop=TRUE useseparateexpansions=TRUE expansionbottom=0.102 istentingbottom=TRUE
SolderMaskExpansion SolderMaskExpansion_2 [HasFootprint('BGAS61C20P11X11_270X412X52') or HasFootprint('AQFN40P700X700X85_HS-99N') or HasFootprint('BGA32C40P6X6_238X238X56') or HasFootprint('QFN40P600X600X90-48N') or HasFootprint('SON40P100X60-8N') or HasFootprint('DFN40P130X120X40-6N') or HasFootprint('CL-2025') or HasFootprint('VM3011') or HasFootprint('WE-TPC_4848')or HasFootprint('XQFN40P180X260X50-16N') or HasFootprint('BGA4C40P2X2_76X76X62') or HasFootprint('CL-2025') or HasFootprint('BGA25C40P5X5_200X200X50') or HasFootprint('BGA9C40P3X3_128X128X54') or HasFootprint('QFN40P600X600X60-48N') or HasFootprint('UFQFN40P140X180X55-10N') or HasFootprint('USB4110')] p2: expansion=0.035 istentingtop=FALSE
SolderMaskExpansion SolderMaskExpansion_3 [HasFootprint('TSQFP50P1600X1600X160-100N') or HasFootprint('BGA12C40P3X4_139X164X40') or HasFootprint('Molex_502774-0891') or HasFootprint('LED_DUAL_0606') or HasFootprint('DFN65P100X40-3L') or HasFootprint('Nordic_QFN50P500X500X90-33N') or HasFootprint('C1608X06L-C1005X04M') or HasFootprint('LED_RGB_0606') or HasFootprint('SM03B-SRSS-TB') or HasFootprint('L-KLS7-TS5401A-1.35-250-T') or HasFootprint('COAXIAL-SWF')] p3: expansion=0.05 istentingtop=FALSE
SolderMaskExpansion SolderMaskExpansion_4 [HasFootprint('DMx299UDJ')] p4: expansion=0.025 istentingtop=FALSE
SolderMaskExpansion [All] p5: expansion=0.075 istentingtop=FALSE
SupplyNets "Schematic Supply Nets_34" [InNet('Shield')] p1: voltage=0.000
SupplyNets "Schematic Supply Nets_33" [InNet('3V3_IND')] p2: voltage=0.000
SupplyNets "Schematic Supply Nets_8" [InNet('1V8_IND')] p3: voltage=0.000
SupplyNets "Schematic Supply Nets_30" [InNet('VDD_nRF91_RES')] p4: voltage=0.000
SupplyNets "Schematic Supply Nets_20" [InNet('VDD_RF_FE_3V3_SP')] p5: voltage=0.000
SupplyNets "Schematic Supply Nets_32" [InNet('VDD_SENS')] p6: voltage=0.000
SupplyNets "Schematic Supply Nets_31" [InNet('VDD_EXP_BRD')] p7: voltage=0.000
SupplyNets "Schematic Supply Nets_29" [InNet('VDD_RF_FE_3V3')] p8: voltage=0.000
SupplyNets "Schematic Supply Nets_28" [InNet('VBAT')] p9: voltage=0.000
SupplyNets "Schematic Supply Nets_27" [InNet('VDD_BMM350')] p10: voltage=0.000
SupplyNets "Schematic Supply Nets_26" [InNet('VDD_BMI270')] p11: voltage=0.000
SupplyNets "Schematic Supply Nets_25" [InNet('VDD_ENV')] p12: voltage=0.000
SupplyNets "Schematic Supply Nets_24" [InNet('PWRIOVDD')] p13: voltage=0.000
SupplyNets "Schematic Supply Nets_23" [InNet('1V8_SW')] p14: voltage=0.000
SupplyNets "Schematic Supply Nets_22" [InNet('1V8')] p15: voltage=0.000
SupplyNets "Schematic Supply Nets_21" [InNet('VDD_ACC')] p16: voltage=0.000
SupplyNets "Schematic Supply Nets_19" [InNet('3V3')] p17: voltage=0.000
SupplyNets "Schematic Supply Nets_18" [InNet('GND')] p18: voltage=0.000
SupplyNets "Schematic Supply Nets_17" [InNet('VDD_nRF53')] p19: voltage=0.000
SupplyNets "Schematic Supply Nets_16" [InNet('VSYS_SW')] p20: voltage=0.000
SupplyNets "Schematic Supply Nets_15" [InNet('PVSS2')] p21: voltage=0.000
SupplyNets "Schematic Supply Nets_14" [InNet('PVSS1')] p22: voltage=0.000
SupplyNets "Schematic Supply Nets_13" [InNet('VBUS')] p23: voltage=0.000
SupplyNets "Schematic Supply Nets_12" [InNet('VDDIO_nRF70')] p24: voltage=0.000
SupplyNets "Schematic Supply Nets_11" [InNet('VOUT_BUCK0')] p25: voltage=0.000
SupplyNets "Schematic Supply Nets_10" [InNet('VDD_BUCK')] p26: voltage=0.000
SupplyNets "Schematic Supply Nets_9" [InNet('VBUS_CONN')] p27: voltage=0.000
SupplyNets "Schematic Supply Nets_7" [InNet('VOUT_BUCK3')] p28: voltage=0.000
SupplyNets "Schematic Supply Nets_6" [InNet('VBUSOUT')] p29: voltage=0.000
SupplyNets "Schematic Supply Nets_5" [InNet('VBAT_nRF70')] p30: voltage=0.000
SupplyNets "Schematic Supply Nets_4" [InNet('VDD_LED')] p31: voltage=0.000
SupplyNets "Schematic Supply Nets_3" [InNet('VDD_nRF91')] p32: voltage=0.000
SupplyNets "Schematic Supply Nets_2" [InNet('VDD_RF_FE_SR')] p33: voltage=0.000
SupplyNets "Schematic Supply Nets_1" [InNet('VSYS')] p34: voltage=0.000
SupplyNets "Schematic Supply Nets" [InNet('VDD_MEM')] p35: voltage=0.000
UnpouredPolygon [All] p1 off:
Width "Width_nRF5340 and nPM6001" [OnLayer('Bottom Layer') and WithinRoom('nRF53') or OnLayer('Mid Layer 4') and WithinRoom('nPM6001')] p1: maxlimit=0.254 minlimit=0.105 preferedwidth=0.254
Width Width_Diff [(InDifferentialPairClass('All Differential Pairs'))] p2: maxlimit=0.165 minlimit=0.15 preferedwidth=0.165
Width Width_RF [InNetClass('RF')] p3: maxlimit=0.638 minlimit=0.035 preferedwidth=0.062 toplayer_minwidth=0.638 toplayer_prefwidth=0.638 midlayer1_maxwidth=0.035 midlayer1_prefwidth=0.035 midlayer2_minwidth=0.062 midlayer2_maxwidth=0.062 midlayer3_minwidth=0.062 midlayer3_maxwidth=0.062 midlayer4_maxwidth=0.035 midlayer4_prefwidth=0.035 bottomlayer_minwidth=0.638 bottomlayer_prefwidth=0.638 impedanceprofiledriven=TRUE impedanceprofileid={C8E51A2C-D176-4063-A735-4B14FCDA7D28} impedanceprofilevalue=50.000000 minimp=50.000000 maximp=50.000000 favimp=50.000000 checkconnectedcopper=TRUE
Width Width_RF_BLE/WIFI [InNetClass('RF_BLE/WIFI')] p4: maxlimit=0.29 minlimit=0.035 preferedwidth=0.062 toplayer_minwidth=0.29 toplayer_prefwidth=0.29 midlayer1_maxwidth=0.035 midlayer1_prefwidth=0.035 midlayer2_minwidth=0.062 midlayer2_maxwidth=0.062 midlayer3_minwidth=0.062 midlayer3_maxwidth=0.062 midlayer4_maxwidth=0.035 midlayer4_prefwidth=0.035 bottomlayer_minwidth=0.29 bottomlayer_prefwidth=0.29 impedanceprofiledriven=TRUE impedanceprofileid={BFD42E9A-6BB2-400D-A7A0-5B5FD1E38EF8} impedanceprofilevalue=50.000000 minimp=50.000000 maximp=50.000000 favimp=50.000000 checkconnectedcopper=TRUE
Width [All] p5: maxlimit=3 minlimit=0.125 preferedwidth=0.125
18 further rules are at their usual default settings.

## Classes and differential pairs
pad class NPTH: H1- H2-
component class nRF53: U6
component class nPM6001: U25
component class pca20065_nrf9151: C1 C2 C3 C4 C5 C6 C10 C31 C32 C33 C35 C36 C103 FB1 L5 M1 Q13 Q14 R1 R2 R54 R106 R107 R108 SB6 TP22 TP23 TP24 TP32 TP33 TP39 TP40 U9
component class pca20065_nrf5340: C12 C13 C15 C16 C17 C18 C19 C20 C21 C22 C23 C24 C25 C26 C27 C28 C29 CR1 F1 L1 L2 L3 L4 R4 R6 R10 R11 R16 SB7 TP5 U6 X1 X2
net class POWER: 1V8_SW NetU25_C5 NetU25_D1 VOUT_BUCK0 VOUT_BUCK3 VSYS_SW
net class RF_BLE/WIFI: ANT NetC24_2 NetC25_2 NetCR1_2 NetF2_1 NetF2_3 NetF2_6 NetU21_9
net class RF: GPS_RF1 GPS_RF2 NetA1_1 NetJ1_1 NetJ1_3 NetU9_5 NetZ1_2 NetZ5_1 NetZ21_1 RF1 RF2 RF3 RF4 RFC
differential pair D:J6: +D:J6_P -D:J6_N
differential pair USB.D: +USB.D_P -USB.D_N

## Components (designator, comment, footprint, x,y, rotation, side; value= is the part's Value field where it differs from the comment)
A1 "NN03-310" NN03-310_RF_ALT1 51.1,17 r270 top locked
A2 "NN03-320" NN03-320 51.1,40.5 r90 top
A3 "NN02-101" NN02-101_Corner 26.5,51.25 r90 top
C1 "15pF" CAPC0603X03L_C 25.008,8.748 r270 top
C2 "100nF" CAPC0603X03L_C 25.583,8.748 r270 top
C3 "47µF" CAPC2012X11L 27.006,10.615 r90 top
C4 "100nF" CAPC0603X03L_C 14.142,18.165 r270 top
C5 "4.7µF" CAPC1005X04L 13.478,17.95 r270 top
C6 "4.7µF" CAPC2012X11L 27.006,13.601 r90 top
C7 "100nF" CAPC0603X03L_C 16.186,11.801 r90 bottom
C8 "2.2µF" CAPC1005X04L_C2 16.326,26.301 r0 top
C9 "1.0nF" CAPC0603X03L_C 14.459,44.726 r180 bottom
C10 "100nF" CAPC0603X03L_C 17.895,8.553 r270 top
C11 "100nF" CAPC0603X03L_C 8.175,29.3 r270 bottom
C12 "100nF" CAPC0603X03L_C 20.775,24.505 r0 bottom
C13 "100nF" CAPC0603X03L_C 20.184,21.555 r270 bottom
C14 "1.0µF" CAPC1005X04L 8.3,27.75 r90 bottom
C15 "1.0µF" CAPC1005X04L 17.425,20.63 r270 bottom
C16 "1.0µF" CAPC1005X04L 15.975,29.905 r180 bottom
C17 "1.0µF" CAPC1005X04L 18.8,29.105 r90 bottom
C18 "2.2nF" CAPC0603X03L_C 20.325,26.23 r0 bottom
C19 "100nF" CAPC0603X03L_C 13.85,21.63 r180 bottom
C20 "100nF" CAPC0603X03L_C 13.85,22.805 r180 bottom
C21 "100nF" CAPC0603X03L_C 19.575,27.655 r90 bottom
C22 "1.0µF" CAPC1005X04L 13.5,28.855 r270 bottom
C23 "1.0µF" CAPC1005X04L 16.2,28.48 r90 bottom
C24 "0.7pF" CAPC0603X03L_C 21.075,25.38 r270 bottom
C25 "N.C." CAPC0603X03L_C_NC 22.775,25.38 r270 bottom
C26 "4.7µF" CAPC1608X06L 12.45,28.58 r90 bottom
C27 "4.7µF" CAPC1608X06L 13.312,25.768 r180 bottom
C28 "100nF" CAPC0603X03L_C 18.55,27.355 r180 bottom
C29 "1.0µF" CAPC1005X04L 15.4,28.48 r90 bottom
C30 "2.2µF" CAPC1608X06L 29.075,38.325 r90 top
C31 "39pF" CAPC0603X03L_C 31.3,38.2 r270 top
C32 "100pF" CAPC0603X03L_C 34.3,40.65 r270 top
C33 "100nF" CAPC0603X03L_C 34.3,39.563 r90 top
C34 "100nF" CAPC0603X03L_C 28.45,5.825 r90 top
C35 "100nF" CAPC0603X03L_C 33.7,38.3 r90 bottom
C36 "100pF" CAPC0603X03L_C 34.3,38.3 r90 bottom
C37 "100nF" CAPC0603X03L_C 26.3,18.05 r270 bottom
C38 "100pF" CAPC0603X03L_C 35.32,4.8 r90 bottom
C39 "100nF" CAPC0603X03L_C 21.605,26.871 r0 top
C40 "100nF" CAPC0603X03L_C 19.9,35.1 r270 bottom
C41 "100nF" CAPC0603X03L_C 27.468,39.875 r270 top
C42 "2.2µF" CAPC1005X04L 27.275,30.725 r90 top
C43 "10nF" CAPC0603X03L_C 7.275,37.75 r270 bottom
C44 "100nF" CAPC0603X03L_C 4.725,37.75 r90 bottom
C45 "1.0µF" CAPC1005X04L 26.425,30.725 r270 top
C46 "1.0µF" CAPC1608X06L 5.831,42.403 r0 bottom
C47 "10µF" CAPC1608X06L 15.225,43.15 r270 bottom
C48 "10µF" CAPC1608X06L 15.225,40.55 r90 bottom
C49 "10µF" CAPC1608X06L 5.831,41.305 r0 bottom
C50 "1.0µF" CAPC1608X06L 5.831,43.5 r0 bottom
C51 "2.2µF" CAPC1608X06L 5.831,39.7 r0 bottom
C52 "10µF" CAPC1005X04L 14.575,45.377 r180 bottom
C53 "10µF" CAPC1608X06L 17.175,38.7 r0 bottom
C54 "10nF" CAPC0603X03L_C 26.725,8.15 r180 top
C55 "100nF" CAPC0603X03L_C 16,7.035 r90 bottom
C56 "100nF" CAPC0603X03L_C 40.174,49.011 r0 bottom
C57 "100nF" CAPC0603X03L_C 38.575,49.011 r0 bottom
C58 "1.0nF" CAPC0603X03L_C 5.704,40.497 r0 bottom
C59 "N.C." CAPC0603X03L_C_NC 25,1.2 r90 top
C60 "0.47µF" CAPC0603X03L_C 25.725,31.15 r90 top
C61 "0.47µF" CAPC0603X03L_C 22.495,40.175 r270 top
C62 "100nF" CAPC0603X03L_C 21.925,40.175 r90 top
C63 "4.7µF" CAPC1608X06L 20.388,39.94 r0 top
C64 "4.7µF" CAPC1608X06L 19.709,32.122 r90 top
C65 "4.7µF" CAPC1608X06L 19.709,29.722 r270 top
C66 "10nF" CAPC0603X03L_C 23.859,31.947 r180 top
C67 "2.2µF" CAPC1608X06L 24.284,31.022 r180 top
C68 "4.7µF" CAPC1608X06L 19.695,38.775 r0 top
C69 "22nF" CAPC0603X03L_C 20.395,37.911 r0 top
C70 "0.22µF" CAPC0603X03L_C 20.395,37.338 r0 top
C71 "2.2µF" CAPC0603X03L_C 20.395,36.765 r0 top
C72 "1.0µF" CAPC1005X04L 19.645,35.524 r0 top
C73 "1.0µF" CAPC1005X04L 19.645,34.7 r0 top
C74 "1.0nF" CAPC0603X03L_C 14.593,39.088 r180 bottom
C75 "100nF" CAPC0603X03L_C 2.975,15.025 r270 bottom
C76 "100nF" CAPC0603X03L_C 0.825,15.025 r90 bottom
C77 "10µF" CAPC1608X06L 13.25,34.825 r90 bottom
C78 "10µF" CAPC1608X06L 11.425,34.15 r180 bottom
C79 "100nF" CAPC0603X03L_C 11.1,37.825 r270 bottom
C80 "10µF" CAPC1608X06L 13.25,32.325 r270 bottom
C81 "4.7µF" CAPC1608X06L 11.425,33 r180 bottom
C82 "1.0µF" CAPC0603X03L_C 15.562,35.395 r0 bottom
C83 "1.0µF" CAPC0603X03L_C 15.462,31.145 r0 bottom
C84 "1.0µF" CAPC0603X03L_C 15.475,31.725 r0 bottom
C85 "1.0µF" CAPC0603X03L_C 17.812,35.42 r0 bottom
C86 "100nF" CAPC0603X03L_C 19.9,34.05 r90 bottom
C87 "100nF" CAPC0603X03L_C 21.525,36.55 r0 bottom
C88 "100nF" CAPC0603X03L_C 19.9,36.15 r90 bottom
C89 "10µF" CAPC1608X06L 18.45,36.875 r90 bottom
C90 "10µF" CAPC1608X06L 21.425,43.275 r270 bottom
C91 "100nF" CAPC0603X03L_C 22.679,24.244 r90 top
C92 "100nF" CAPC0603X03L_C 17.95,25.516 r270 top
C93 "100nF" CAPC0603X03L_C 15.65,25.116 r270 top
C94 "10µF" CAPC1608X06L 13.606,47.525 r180 top
C95 "100pF" CAPC1005X04L 11.564,49.666 r90 top
C96 "10µF" CAPC1608X06L 19.878,40.142 r270 bottom
C97 "100pF" CAPC1005X04L 23.951,40.142 r270 bottom
C98 "100pF" CAPC1005X04L 5.126,46.617 r270 bottom
C99 "10pF" CAPC0603X03L_C 10.857,26.045 r0 bottom
C100 "10pF" CAPC0603X03L_C 9.735,26.045 r180 bottom
C101 "10pF" CAPC0603X03L_C 2.732,37.314 r270 bottom
C102 "10pF" CAPC0603X03L_C 2.069,37.314 r270 bottom
C103 "10µF" CAPC1608X06L 20.274,9.041 r0 top
CR1 "EZA-EG1N50AC" RESC0603X03L_C 24.291,27.676 r0 bottom
D3 "TPD3F303DPVR" SON50P210X160X65_HS-9N 26.4,3.4 r90 top
F1 "SAFFB2G45MA0F0A" SAFFB2G45MA0F0A 24.3,26.451 r90 bottom
F2 "LFD_Diplexer" CAF-50P160X80-6N 19.95,43.5 r90 top value=LFD182G45DCJD247
FB1 "120R/0.7A" INDC1608X06L 22.657,9.041 r180 top
FB2 "120R/0.55A" INDC1005X04L 6,37.525 r180 bottom
FB3 "BLM21AG102SN1D" INDC2012X11L 12.931,49.566 r90 top
FB4 "BLM21AG102SN1D" INDC2012X11L 21.932,39.467 r0 bottom
FB5 "BLM21AG102SN1D" INDC2012X11L 6.547,46.872 r270 bottom
Fid1 "Fiducial mark" Fiducial_Round-Square 6.5,2.5 r180 top value=N.A.
Fid2 "Fiducial mark" Fiducial_Round-Square 51,51 r0 top value=N.A.
H1 "MountingHole_NPTH" MountingHole_3.2_M3 3.25,3.25 r180 top value=MountingHole_3.2_M3
H2 "MountingHole_NPTH" MountingHole_3.2_M3 46,49.75 r180 top locked value=MountingHole_3.2_M3
J1 "MM8130-2600" COAXIAL-SWF 30.8,12.4 r0 top
J2 "MM8130-2600" COAXIAL-SWF 19.768,47.623 r270 top
J3 "HDR-3, 1mm" SM03B-SRSS-TB 8.5,48.8 r270 bottom locked
J4 "SF72S006VBxR2500" SF72S006VBxR2500 20.625,0.9 r180 bottom locked value=SF72S006VBDR2500
J6 "USB-C 2.0" USB4110 5.78,30.45 r90 bottom locked
L1 "10µH" INDC1608X06L 17.85,28.78 r270 bottom
L2 "10µH" INDC1608X06L 14.45,28.455 r270 bottom
L3 "2.2nH" INDC0603X03L_C 20.225,25.08 r180 bottom
L4 "2.2nH" INDC0603X03L_C 21.925,25.08 r180 bottom
L5 "9.1nH" INDC1005X04L_WW 30.4,40.65 r90 top
L6 "3.3µH" INDC2520X10N 21.575,30.212 r270 top
L7 "2.2µH" INDC2016X10N 17.1,43.625 r270 bottom
L8 "2.2µH" INDC2016X10N 17.6,40.575 r180 bottom
L9 "2.2µH" INDC2016X10N 10.975,35.925 r180 bottom
L10 "470nH" INDC1608X06L 11.425,31.85 r180 bottom
LABEL1 "12x38mm" LabelSilk_12x38 34.875,43.414 r270 top
LED1 "LED RGB" LED_RGB_0606 50,48 r0 top locked
LED2 "LED RGB" OVSRRGBCC3_Side 2,20.45 r0 top
LED3 "LED RGB" OVSRRGBCC3_Side 2,30.45 r0 top
LOGO1 "WEE Symbol" WEE_3x4.5mm 33.654,50.847 r0 top
LOGO2 "Nordic Logo" NORDIC_LOGO_LYING 2.968,36.203 r0 top
M1 "nRF9151-LACAA1A" LGA50P1210X1110X130-113N 20.267,15.7 r0 top
NT1 "Net tie" "2 PIN STARPOINT" 14.603,43.95 r180 bottom net-tie
NT2 "Net tie" "2 PIN STARPOINT" 15.772,38.9 r180 bottom net-tie
P1 "HDR-4, 1mm" SM04B-SRSS-TB 1.2,20.45 r90 bottom locked
P8 "Pin Header 2x5" HDR_2x5-SMD-1.27mm-ANG 6.7,9.7 r270 top locked
P9 "Card Edge, 0.8mm" 10056847-101LF 8.25,9.7 r90 bottom locked
Q1 "RV2C010UNT2L" DFN65P100X40-3L 8.95,21.85 r90 bottom
Q2 "DMN2990UDJ" DMx299UDJ 10.586,23.109 r270 bottom
Q3 "RV2C010UNT2L" DFN65P100X40-3L 48.269,49.654 r270 bottom
Q4 "DMN2990UDJ" DMx299UDJ 48,47.5 r90 bottom
Q5 "RV2C010UNT2L" DFN65P100X40-3L 19.175,42.525 r90 bottom
Q6 "DMC2990UDJ" DMx299UDJ 6.504,49.155 r0 bottom
Q13 "DMC2990UDJ" DMx299UDJ 19,10.625 r0 bottom
Q14 "RV2C010UNT2L" DFN65P100X40-3L 19.5,9.175 r270 bottom
R1 "10k" RESC0603X03L_C 20.242,10.851 r270 bottom
R2 "1k" RESC0603X03L_C 18.48,8.553 r90 top
R3 "1M0" RESC0603X03L_C 8.7,35 r180 bottom
R4 "150R" RESC0603X03L_C 19.605,21.555 r270 bottom
R5 "0R" RESC0603X03L_C 1.854,14.787 r270 top
R6 "150R" RESC0603X03L_C 20.891,21.555 r270 bottom
R7 "47k" RESC0603X03L_C 8.45,37.825 r270 bottom
R8 "330k" RESC0603X03L_C 9.05,37.825 r270 bottom
R9 "1M0" RESC0603X03L_C 17.125,36 r180 bottom
R10 "2R2" RESC1005X04L 12.75,30.232 r0 bottom
R11 "0R" RESC0603X03L_C 18.475,21.05 r90 bottom
R12 "100R" RESC0603X03L_C 49.25,48.6 r0 bottom
R13 "39R" RESC0603X03L_C 49.25,48 r0 bottom
R14 "39R" RESC0603X03L_C 49.25,47.4 r0 bottom
R15 "4M7" RESC0603X03L_C 1.852,13.623 r270 top
R16 "150R" RESC0603X03L_C 21.462,21.555 r270 bottom
R17 "10k" RESC0603X03L_C 17.84,5.422 r180 bottom
R18 "100k" RESC0603X03L_C 16.705,5.422 r180 bottom
R19 "100R" RESC0603X03L_C 9.05,23.375 r180 bottom
R20 "39R" RESC0603X03L_C 9.05,22.8 r180 bottom
R21 "39R" RESC0603X03L_C 9.05,23.95 r180 bottom
R22 "4k7" RESC0603X03L_C 11.323,14.765 r90 top
R23 "4k7" RESC0603X03L_C 10.723,14.765 r90 top
R24 "0.1R" RESC1005X04L 11.4,16.075 r180 bottom
R25 "N.C." RESC0603X03L_C_NC 20.761,41.099 r270 bottom
R26 "1k" RESC0603X03L_C 19.9,37.225 r270 bottom
R27 "0R" RESC0603X03L_C 27.6,16.575 r90 bottom
R28 "0R" RESC0603X03L_C 27.325,17.4 r0 bottom
R29 "0R" RESC0603X03L_C 27.6,18.225 r270 bottom
R30 "1M0" RESC0603X03L_C 7.726,46.343 r90 bottom
R31 "0R" RESC0603X03L_C 10.572,26.843 r90 bottom
R32 "0R" RESC0603X03L_C 18.942,5.422 r180 bottom
R33 "1M0" RESC0603X03L_C 23.011,41.574 r90 bottom
R34 "0R" RESC0603X03L_C 10.02,26.843 r90 bottom
R38 "1M0" RESC0603X03L_C 11.15,21.5 r270 bottom
R41 "1M0" RESC0603X03L_C 9.75,21.5 r270 bottom
R42 "1M0" RESC0603X03L_C 10.45,21.5 r270 bottom
R43 "100k" RESC0603X03L_C 26.6,18.9 r0 bottom
R44 "1M0" RESC0603X03L_C 48.329,50.601 r180 bottom
R45 "1M0" RESC0603X03L_C 46.975,47.5 r270 bottom
R46 "1M0" RESC0603X03L_C 48.071,48.708 r180 bottom
R49 "1M0" RESC0603X03L_C 26.725,8.725 r0 top
R50 "100k" RESC0603X03L_C 26.3,16.95 r90 bottom
R53 "100k" RESC0603X03L_C 24.842,32.733 r270 bottom
R54 "1M0" RESC0603X03L_C 33.1,38.3 r90 bottom
R56 "N.C." RESC0603X03L_C_NC 29.075,39.878 r180 bottom
R58 "100k" RESC0603X03L_C 29.063,35.65 r0 top
R59 "100k" RESC0603X03L_C 29.063,35.1 r0 top
R60 "100k" RESC0603X03L_C 29.063,36.775 r180 top
R61 "100k" RESC0603X03L_C 24.587,30.157 r0 top
R62 "100k" RESC0603X03L_C 19.975,42.525 r90 bottom
R64 "100k" RESC0603X03L_C 5.254,49.08 r270 bottom
R106 "10k" RESC0603X03L_C 19.128,12.235 r0 bottom
R107 "100k" RESC0603X03L_C 19.128,11.654 r0 bottom
R108 "N.C." RESC0603X03L_C_NC 18.679,9.276 r270 bottom
SB1 "Solderbridge" Solderbridge 33.088,13.075 r0 bottom
SB4 "Solderbridge" Solderbridge_Shorted 23.173,26.922 r270 top net-tie
SB5 "Solderbridge" Solderbridge_Shorted 35.75,48.538 r0 bottom net-tie
SB6 "Solderbridge" Solderbridge_Shorted 18.443,7.351 r180 top net-tie
SB7 "Solderbridge" Solderbridge_Shorted 6.555,46.53 r90 top net-tie
SB8 "Solderbridge" Solderbridge_Shorted 6.144,15.635 r0 top net-tie
SB9 "Solderbridge" Solderbridge_Shorted 6.144,16.948 r0 top net-tie
SB10 "Solderbridge" Solderbridge_Shorted 18.867,25.578 r270 top net-tie
SBI2 "Solderbridge" Solderbridge 33.088,11.575 r180 bottom
ST1 "Net tie" "2 PIN STARPOINT" 22.445,27.506 r180 top net-tie
ST2 "Net tie" "2 PIN STARPOINT" 24.918,39.628 r180 bottom net-tie
ST3 "Net tie" "2 PIN STARPOINT" 24.918,39.219 r180 bottom net-tie
ST4 "Net tie" "2 PIN STARPOINT" 18.841,26.637 r90 top net-tie
ST5 "Net tie" "2 PIN STARPOINT" 21.925,42.859 r180 bottom net-tie
ST7 "Net tie" "2 PIN STARPOINT" 20.253,37.713 r90 bottom net-tie
ST9 "Net tie" "2 PIN STARPOINT" 19.1,37.075 r90 bottom net-tie
SW1 "Switch" JS102011JAQN 2.35,43.05 r90 bottom locked
SW2 "AYZ0102AGRLC" AYZ0102AGRLC 16,1.8 r180 bottom locked
SW3 "PB SW" L-KLS7-TS6616B-2.5-160-T 27.8,26.5 r0 top locked
SW4 "L-KLS7-TS5401A-1.35-250-T" L-KLS7-TS5401A-1.35-250-T 5.85,51.5 r0 bottom
TP1 "Ø1.5mm,SMD" TP_SMD_D1.5mm 10.5,6.5 r0 top
TP2 "Ø1.5mm,SMD" TP_SMD_D1.5mm 6.5,24.927 r270 top
TP3 "Ø1.5mm,SMD" TP_SMD_D1.5mm 3.5,24.927 r270 top
TP4 "Ø1.5mm,SMD" TP_SMD_D1.5mm 7,49 r180 top
TP5 "Ø1.5mm,SMD" TP_SMD_D1.5mm 12.946,11.588 r180 top
TP6 "Ø0.7mm,SMD" TP_SMD_D0.7mm 29.475,33.95 r270 bottom
TP7 "Ø0.7mm,SMD" TP_SMD_D0.7mm 19.643,22.444 r90 top
TP8 "Ø1.0mm,SMD" TP_SMD_D1.0mm 29.105,42.194 r180 top
TP9 "Ø1.5mm,SMD" TP_SMD_D1.5mm 8.642,21.927 r270 top
TP10 "Ø1.5mm,SMD" TP_SMD_D1.5mm 8.642,18.927 r270 top
TP11 "Ø1.0mm,SMD" TP_SMD_D1.0mm 20.025,43.8 r0 bottom
TP12 "Ø1.5mm,SMD" TP_SMD_D1.5mm 9.5,31.95 r0 top
TP13 "Ø1.5mm,SMD" TP_SMD_D1.5mm 12.5,28.95 r0 top
TP14 "Ø1.5mm,SMD" TP_SMD_D1.5mm 9.5,24.927 r0 top
TP15 "Ø1.5mm,SMD" TP_SMD_D1.5mm 9.5,28.95 r180 top
TP16 "Ø1.5mm,SMD" TP_SMD_D1.5mm 29,3.5 r0 top
TP17 "Ø1.5mm,SMD" TP_SMD_D1.5mm 5.642,21.927 r90 top
TP18 "Ø1.5mm,SMD" TP_SMD_D1.5mm 12.5,24.927 r90 top
TP19 "Ø1.5mm,SMD" TP_SMD_D1.5mm 5.642,18.927 r90 top
TP20 "Ø0.7mm,SMD" TP_SMD_D0.7mm 22.643,22.444 r90 top
TP21 "Ø1.0mm,SMD" TP_SMD_D1.0mm 33.54,21.795 r180 bottom
TP22 "Ø1.0mm,SMD" TP_SMD_D1.0mm 29.459,33.471 r180 top
TP23 "Ø1.0mm,SMD" TP_SMD_D1.0mm 16.2,17.9 r0 bottom
TP24 "Ø1.0mm,SMD" TP_SMD_D1.0mm 32.172,30.596 r180 top
TP25 "Ø1.0mm,SMD" TP_SMD_D1.0mm 33.54,25.605 r180 bottom
TP26 "Ø1.0mm,SMD" TP_SMD_D1.0mm 28.46,21.795 r180 bottom
TP27 "Ø1.5mm,SMD" TP_SMD_D1.5mm 13.5,6.5 r180 top
TP28 "Ø1.5mm,SMD" TP_SMD_D1.5mm 16.5,3.5 r180 top
TP29 "Ø1.5mm,SMD" TP_SMD_D1.5mm 16.5,6.5 r180 top
TP30 "Ø1.5mm,SMD" TP_SMD_D1.5mm 6.5,31.95 r0 top
TP31 "Ø1.5mm,SMD" TP_SMD_D1.5mm 6.5,28.95 r0 top
TP32 "Ø1.5mm,SMD" TP_SMD_D1.5mm 10.5,3.5 r180 top
TP33 "Ø1.5mm,SMD" TP_SMD_D1.5mm 13.5,3.5 r180 top
TP34 "Ø1.0mm,SMD" TP_SMD_D1.0mm 25.92,21.795 r180 bottom
TP35 "Ø1.5mm,SMD" TP_SMD_D1.5mm 3.726,49 r0 top
TP36 "Ø1.5mm,SMD" TP_SMD_D1.5mm 30.72,19.925 r0 top
TP37 "Ø0.7mm,SMD" TP_SMD_D0.7mm 28.917,32.798 r270 bottom
TP38 "Ø0.7mm,SMD" TP_SMD_D0.7mm 28.667,30.884 r270 bottom
TP39 "Ø0.7mm,SMD" TP_SMD_D0.7mm 18.077,15.616 r180 bottom
TP40 "Ø0.7mm,SMD" TP_SMD_D0.7mm 16.61,15.616 r180 bottom
U1 "NLAS5223BMNR2G" UFQFN40P140X180X55-10N 16.386,9.906 r270 bottom
U2 "TCK106AG" BGA4C40P2X2_76X76X62 9.45,34 r0 bottom
U3 "TCK106AG" BGA4C40P2X2_76X76X62 12.35,21.55 r0 bottom
U4 "TCK106AG" BGA4C40P2X2_76X76X62 14.6,12.7 r270 bottom
U5 "TCK108AG" BGA4C40P2X2_76X76X62 21.761,41.099 r270 bottom
U6 "nRF5340-CMAAD0" BGA95C35P12X11_439X399X49 17.15,24.38 r180 bottom
U7 "GD25LE255ELIG" BGA32C50P6X8_350X400X50 23.425,17.525 r90 bottom
U8 "ECMF02-4CMX8" UFDFN50P120X250X55-8N 10.277,28.323 r270 bottom
U9 "SKY65943-11" SKY65943-11 32.5,40.4 r180 top
U10 "TCK106AG" BGA4C40P2X2_76X76X62 29.088,40.215 r180 top
U11 "nPM1300-QEAAC0" Nordic_QFN50P500X500X90-33N 10.8,41.6 r180 bottom
U12 "FSA2466UMX" XQFN40P180X260X50-16N 17.95,6.975 r270 bottom
U13 "TCK106AG" BGA4C40P2X2_76X76X62 29.075,38.828 r180 bottom
U14 "TCK106AG" BGA4C40P2X2_76X76X62 3.319,14.864 r0 top
U15 "MFFx_M2M_UICC" SON127P600X90_HS-8N 21.9,4.9 r270 top locked value="M2M UICC"
U16 "NX3DV2567" XQFN40P180X260X50-16N 26.4,6.325 r270 top
U17 "QM13345" PQFN40P110X150X50-10N 32.718,5.5 r90 top
U18 "BMI270" BMI270 21.143,25.029 r90 top
U20 "ADXL367" LGA50P220X230X97-12N 21.575,34.825 r180 bottom
U21 "nRF7002-QFAAB0" QFN40P600X600X60-48N 24.75,35.775 r270 top value=nRF7002-QFAA
U22 "BGS12xN6" TSNP-6-8 19.45,41.45 r90 top value=BGS12WN6E6327XTSA1
U23 "BME688" BME680 39.25,51.011 r90 bottom
U24 "TXS0102YZPR" BGA8C50P2X4_89X189X50 1.9,15.025 r180 bottom
U25 "nPM6001-CAAAF0" BGA45C40P5X9_217X364X49 16.075,33.575 r90 bottom locked
U26 "BMM350" BGA9C40P3X3_128X128X54 16.788,24.831 r180 top
X1 "32MHz" BT-XTAL_2016 21.58,28.06 r90 bottom
X2 "32.768kHz" XTAL_2012 13.07,24.29 r180 bottom
X3 "40MHz" BT-XTAL_1612 18.47,37.2 r90 top
Z1 "6.0pF" C1608X06L-C1005X04M#1 33.219,8.142 r90 top
Z2 "0R" C1608X06L-C1005X04M#1 31.719,8.142 r90 top
Z3 "2.1pF" C1608X06L-C1005X04M#2 33.219,2.86 r270 top
Z4 "3.7nH" C1608X06L-C1005X04M#2 31.719,2.86 r270 top
Z5 "0R" C1608X06L-C1005X04M#3 30.219,6.512 r270 top
Z6 "3.7nH" C1608X06L-C1005X04M#3 29.609,8.112 r180 top
Z7 "0R" C1608X06L-C1005X04M#3 30.219,9.712 r270 top
Z9 "0.3pF" C1608X06L-C1005X04M#4 47.525,5.25 r90 top
Z10 "12nH" C1608X06L-C1005X04M#4 48.75,5.25 r90 top
Z11 "N.C." C1608X06L-C1005X04M#4 47.525,28.75 r90 top
Z12 "N.C." C1608X06L-C1005X04M#4 48.75,28.75 r90 top
Z21 "2.8nH" C1608X06L-C1005X04M#4 35.4,45 r0 top
Z22 "2.5nH" C1608X06L-C1005X04M#4 33.1,45 r180 top
Z23 "0R" C1608X06L-C1005X04M#4 33.7,43.2 r90 top
Z31 "3.8nH" C1608X06L-C1005X04M#4 21.575,52.15 r0 top
Z32 "N.C." C1608X06L-C1005X04M#4 19.894,51.54 r90 top
Z33 "6.0nH" C1608X06L-C1005X04M#4 18.191,52.15 r0 top
Z34 "0.4pF" C1608X06L-C1005X04M#4 16.971,51.001 r180 top
Z35 "1.8pF" C1608X06L-C1005X04M#4 17.581,49.329 r90 top
Z36 "N.C." C1608X06L-C1005X04M#4 16.972,47.623 r180 top
Z81 "0R" C1608X06L-C1005X04M#4 37.457,3.75 r270 top
Z82 "0R" C1608X06L-C1005X04M#4 38.715,3.75 r270 top

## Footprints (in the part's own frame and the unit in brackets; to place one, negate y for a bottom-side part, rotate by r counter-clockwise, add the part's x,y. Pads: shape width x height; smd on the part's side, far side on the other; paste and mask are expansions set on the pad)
"2 PIN STARPOINT" [mil]
  round 5.98 smd paste-196.85 mask-196.85: 1(8,0) 2(-8,0)
  Top Layer region: -11,3 11,3 11,-3 -11,-3
10056847-101LF [mm]
  rect 0.5x2 smd paste-0.05 mask+0.025: 1(-3.4,-4.1) 2(-2.6,-4.1) 3(-1.8,-4.1) 4(-1,-4.1) 5(-0.2,-4.1) 6(0.6,-4.1) 7(1.4,-4.1) 8(2.2,-4.1) 9(3,-4.1) 10(3.8,-4.1) 11(3.4,4.1) 12(2.6,4.1) 13(1.8,4.1) 14(1,4.1) 15(0.2,4.1) 16(-0.6,4.1) 17(-1.4,4.1) 18(-2.2,4.1) 19(-3,4.1) 20(-3.8,4.1)
  round 1.55 hole 1.55 unplated mask+0: ""(-4.8,0) ""(4.8,0)
  silkscreen extent -5.5,-3.9 5.5,3.9, body extent -5.5,-4.5 5.5,4.53, height 5.28
AYZ0102AGRLC [mm] "Slide Switches - SPDT, SMD, ON-ON"
  round 0.85 hole 0.85 unplated: 0(-1.5,0) 0(1.5,0)
  rect 1x1.2 smd: 1(-2.5,2.6) 2(0,2.6) 3(2.5,2.6)
  silkscreen extent -3.6,-2.5 3.6,1.5, body extent -3.6,-2.5 3.6,2.8, height 1.5
BGA4C40P2X2_76X76X62 [mm] "BGA, 4-Leads, Body 0.8x0.8mm,  Pitch 0.40mm"
  round 0.235 smd mask+0.04: A1(-0.2,0.2) A2(0.2,0.2) B1(-0.2,-0.2) B2(0.2,-0.2)
  silkscreen extent -0.74,-0.45 0.45,0.74, body extent -0.39,-0.39 0.4,0.4, height 0.55
BGA8C50P2X4_89X189X50 [mm] "BGA, 8-Leads, Body 0,89x1,89mmx0,50mm, Pitch 0,50mm"
  round 0.17 smd: A1(-0.25,0.75) A2(0.25,0.75) B1(-0.25,0.25) B2(0.25,0.25) C1(-0.25,-0.25) C2(0.25,-0.25) D1(-0.25,-0.75) D2(0.25,-0.75)
  silkscreen extent -0.6,1 -0.5,1.1, body extent -0.45,-0.94 0.45,0.94, height 0.5
BGA9C40P3X3_128X128X54 [mm] "BGA, 9-Leads, Body 1,28x1,28mmx0,54mm, Pitch 0,40mm"
  round 0.22 smd: A1(-0.4,0.4) A2(0,0.4) A3(0.4,0.4) B1(-0.4,0) B2(0,0) B3(0.4,0) C1(-0.4,-0.4) C2(0,-0.4) C3(0.4,-0.4)
  silkscreen extent -0.79,0.7 -0.7,0.79, body extent -0.64,-0.64 0.64,0.64, height 0.54
BGA32C50P6X8_350X400X50 [mm] "BGA, 32-Leads, Body 3.50x4.00mmx0.50mm, Pitch 0.50mm"
  round 0.25 smd: A1(-1.25,1.75) A2(-0.75,1.75) A5(0.75,1.75) A6(1.25,1.75) B1(-1.25,1.25) B2(-0.75,1.25) B5(0.75,1.25) B6(1.25,1.25) C3(-0.25,0.75) C4(0.25,0.75) D1(-1.25,0.25) D2(-0.75,0.25) D3(-0.25,0.25) D4(0.25,0.25) D5(0.75,0.25) D6(1.25,0.25) E1(-1.25,-0.25) E2(-0.75,-0.25) E3(-0.25,-0.25) E4(0.25,-0.25) E5(0.75,-0.25) E6(1.25,-0.25) F3(-0.25,-0.75) F4(0.25,-0.75) G1(-1.25,-1.25) G2(-0.75,-1.25) G5(0.75,-1.25) G6(1.25,-1.25) H1(-1.25,-1.75) H2(-0.75,-1.75) H5(0.75,-1.75) H6(1.25,-1.75)
  silkscreen extent -2.18,-2.08 1.83,2.44, body extent -1.75,-2 1.75,2, height 0.5
BGA45C40P5X9_217X364X49 [mm] "BGA, 45-Leads, Body 2.17x3.64mmx0.49mm, Pitch 0.40mm"
  round 0.22 smd mask+0.05: A1(-0.84,1.56) A2(-0.42,1.56) A3(0,1.56) A4(0.42,1.56) A5(0.84,1.56) B1(-0.84,1.17) B2(-0.42,1.17) B3(0,1.17) B4(0.42,1.17) B5(0.84,1.17) C1(-0.84,0.78) C2(-0.42,0.78) C3(0,0.78) C4(0.42,0.78) C5(0.84,0.78) D1(-0.84,0.39) D2(-0.42,0.39) D3(0,0.39) D4(0.42,0.39) D5(0.84,0.39) E1(-0.84,0) E2(-0.42,0) E3(0,0) E4(0.42,0) E5(0.84,0) F1(-0.84,-0.39) F2(-0.42,-0.39) F3(0,-0.39) F4(0.42,-0.39) F5(0.84,-0.39) G1(-0.84,-0.78) G2(-0.42,-0.78) G3(0,-0.78) G4(0.42,-0.78) G5(0.84,-0.78) H1(-0.84,-1.17) H2(-0.42,-1.17) H3(0,-1.17) H4(0.42,-1.17) H5(0.84,-1.17) J1(-0.84,-1.56) J2(-0.42,-1.56) J3(0,-1.56) J4(0.42,-1.56) J5(0.84,-1.56)
  silkscreen extent -1.39,-1.91 1.21,2.13, body extent -1.14,-1.85 1.14,1.84, height 0.41
BGA95C35P12X11_439X399X49 [mm] "BGA, 95-Leads, Body 4.39x3.99mmx0.49mm, Pitch 0.35mm"
  round 0.2 smd mask+0.05: A1(-1.925,1.75) A2(-1.575,1.75) A3(-1.225,1.75) A5(-0.525,1.75) A7(0.175,1.75) A9(0.875,1.75) A11(1.575,1.75) A12(1.925,1.75) B1(-1.925,1.4) B2(-1.575,1.4) B4(-0.875,1.4) B5(-0.525,1.4) B6(-0.175,1.4) B7(0.175,1.4) B8(0.525,1.4) B9(0.875,1.4) B10(1.225,1.4) B11(1.575,1.4) B12(1.925,1.4) C2(-1.575,1.05) C4(-0.875,1.05) C5(-0.525,1.05) C6(-0.175,1.05) C7(0.175,1.05) C8(0.525,1.05) C9(0.875,1.05) C10(1.225,1.05) C11(1.575,1.05) D1(-1.925,0.7) D2(-1.575,0.7) D10(1.225,0.7) D11(1.575,0.7) D12(1.925,0.7) E2(-1.575,0.35) E3(-1.225,0.35) E4(-0.875,0.35) E5(-0.525,0.35) E6(-0.175,0.35) E7(0.175,0.35) E8(0.525,0.35) E10(1.225,0.35) E11(1.575,0.35) F1(-1.925,0) F2(-1.575,0) F3(-1.225,0) F5(-0.525,0) F6(-0.175,0) F7(0.175,0) F8(0.525,0) F10(1.225,0) F11(1.575,0) F12(1.925,0) G2(-1.575,-0.35) G3(-1.225,-0.35) G5(-0.525,-0.35) G6(-0.175,-0.35) G7(0.175,-0.35) G8(0.525,-0.35) G10(1.225,-0.35) G11(1.575,-0.35) H1(-1.925,-0.7) H2(-1.575,-0.7) H3(-1.225,-0.7) H10(1.225,-0.7) H11(1.575,-0.7) H12(1.925,-0.7) J2(-1.575,-1.05) J3(-1.225,-1.05) J4(-0.875,-1.05) J5(-0.525,-1.05) J6(-0.175,-1.05) J7(0.175,-1.05) J8(0.525,-1.05) J9(0.875,-1.05) J10(1.225,-1.05) J11(1.575,-1.05) K1(-1.925,-1.4) K2(-1.575,-1.4) K3(-1.225,-1.4) K4(-0.875,-1.4) K5(-0.525,-1.4) K6(-0.175,-1.4) K7(0.175,-1.4) K8(0.525,-1.4) K9(0.875,-1.4) K10(1.225,-1.4) K11(1.575,-1.4) K12(1.925,-1.4) L1(-1.925,-1.75) L3(-1.225,-1.75) L5(-0.525,-1.75) L7(0.175,-1.75) L9(0.875,-1.75) L11(1.575,-1.75) L12(1.925,-1.75)
  silkscreen extent -2.38,-1.93 2.26,2.31, body extent -2.13,-1.93 2.26,2.06, height 0.41
BME680 [mm]
  rect 0.4x0.4 smd mask+0.1: 1(1.2,1.2) 2(1.2,0.4) 3(1.2,-0.4) 4(1.2,-1.2) 5(-1.2,-1.2) 6(-1.2,-0.4) 7(-1.2,0.4) 8(-1.2,1.2)
  silkscreen extent -1.58,-1.58 1.82,1.83, body extent -1.5,-1.5 1.5,1.5, height 0.93
BMI270 [mm] "Description 6-axis, smart, low-power, inertial measurement unit"
  rect 0.475x0.25 smd: 1(-1.162,0.75) 2(-1.162,0.25) 3(-1.162,-0.25) 4(-1.162,-0.75) 8(1.162,-0.75) 9(1.162,-0.25) 10(1.162,0.25) 11(1.162,0.75)
  rect 0.25x0.475 smd: 5(-0.5,-0.913) 6(0,-0.913) 7(0.5,-0.913) 12(0.5,0.913) 13(0,0.913) 14(-0.5,0.913)
  silkscreen extent -1.76,-1.25 1.5,1.51, body extent -1.5,-1.25 1.5,1.25, height 0.7
BT-XTAL_1612 [mm] "Crystal 1.6 x 1.2 mm"
  rect 0.65x0.55 smd: 1(-0.575,-0.425) 2(0.575,-0.425) 3(0.575,0.425) 4(-0.575,0.425)
  silkscreen extent -0.88,-0.68 0.88,0.68, body extent -0.83,-0.63 0.83,0.63, height 0.41
BT-XTAL_2016 [mm] "Crystal 2.0 x 1.6 mm"
  rect 0.95x0.85 smd: 1(-0.725,-0.575) 2(0.725,-0.575) 3(0.725,0.575) 4(-0.725,0.575)
  silkscreen extent -1.08,-0.88 1.08,0.88, body extent -1.05,-0.85 1.05,0.85, height 0.56
C1608X06L-C1005X04M#1 [mm] "Chip Capacitor, 2-Leads, Body 1.6x0.8mm, IPC High Density"
  rect 1x1 smd: 1(-0.64,0)
  rect 0.5x1 smd: 2(0.61,0)
  Mid Layer 1 keep-out region: -1.122,-0.575 1.128,-0.575 1.128,0.575 -1.122,0.575
  Mid Layer 2 keep-out region: -1.122,-0.575 1.128,-0.575 1.128,0.575 -1.122,0.575
  silkscreen extent -1.05,-0.5 1.05,0.5, body extent -0.8,-0.4 0.8,0.4, height 0.86
C1608X06L-C1005X04M#2 [mm] "Chip Capacitor, 2-Leads, Body 1.6x0.8mm, IPC High Density"
  rect 1x1 smd: 1(-0.642,0)
  rect 0.5x1 smd: 2(0.61,0)
  Mid Layer 1 keep-out region: -1.125,-0.579 1.125,-0.579 1.125,0.571 -1.125,0.571
  Mid Layer 2 keep-out region: -1.125,-0.579 1.125,-0.579 1.125,0.571 -1.125,0.571
  silkscreen extent -1.05,-0.5 1.05,0.5, body extent -0.8,-0.4 0.8,0.4, height 0.86
C1608X06L-C1005X04M#3 [mm] "Chip Capacitor, 2-Leads, Body 1.6x0.8mm, IPC High Density"
  rect 1x1 smd: 1(-0.61,0) 2(0.61,0)
  Mid Layer 1 keep-out region: -1.125,-0.576 1.125,-0.576 1.125,0.574 -1.125,0.574
  Mid Layer 2 keep-out region: -1.125,-0.576 1.125,-0.576 1.125,0.574 -1.125,0.574
  silkscreen extent -1.05,-0.5 1.05,0.5, body extent -0.8,-0.4 0.8,0.4, height 0.86
C1608X06L-C1005X04M#4 [mm] "Chip Capacitor, 2-Leads, Body 1.6x0.8mm, IPC High Density"
  rect 0.61x0.71 smd: 1(-0.61,0) 2(0.61,0)
  rect 0.46x0.61 smd: 1(-0.485,0) 2(0.485,0)
  Mid Layer 1 keep-out region: -1.127,-0.575 1.123,-0.575 1.123,0.575 -1.127,0.575
  Mid Layer 2 keep-out region: -1.127,-0.575 1.123,-0.575 1.123,0.575 -1.127,0.575
  silkscreen extent -1.05,-0.5 1.05,0.5, body extent -0.8,-0.4 0.8,0.4, height 0.86
CAF-50P160X80-6N [mm] "Chip Array, Flat, 6-Leads, Pitch 0,50mm,  Body 1,60x0,80mm,  IPC Medium Density"
  rect 0.5x0.25 smd mask+0.051: 1(-0.45,0.5) 2(-0.45,0) 3(-0.45,-0.5) 5(0.45,-0.5) 6(0.45,0) 7(0.45,0.5)
  Top Layer region: 1.025,0.375 0.2,0.375 0,0.175 0,-0.175 0.2,-0.375 1.025,-0.375 1.175,-0.525 1.175,-0.95 0.15,-0.95 0,-0.8 0,-0.375 -0.25,-0.125 -0.8,-0.125 -0.9,-0.225 -1,-0.225 -1,0.225 -0.9,0.225 -0.8,0.125 -0.25,0.125 0,0.375 0,0.8 0.15,0.95 1.175,0.95 1.175,0.525
  silkscreen extent -1.1,-1 1,1.02, body extent -0.5,-0.88 0.5,0.88, height 0.67
CAPC0603X03L_C [mm] "Chip Capacitor, 2-Leads, Body 0.6x0.3mm, IPC High Density"
  rect 0.27x0.3 smd mask+0.05: 1(-0.285,0) 2(0.285,0)
  silkscreen extent -0.49,-0.22 0.49,0.22, body extent -0.3,-0.15 0.31,0.15, height 0.3
CAPC0603X03L_C_NC [mm] "Chip Capacitor, 2-Leads, Body 0.6x0.3mm, IPC High Density"
  rect 0.27x0.3 smd mask+0.05: 1(-0.285,0) 2(0.285,0)
  silkscreen extent -0.49,-0.22 0.49,0.22
CAPC1005X04L [mm] "Chip Capacitor, 2-Leads, Body 1.0x0.5mm, IPC High Density"
  rect 0.6x0.5 smd: 1(-0.5,0) 2(0.5,0)
  silkscreen extent -0.9,-0.35 0.9,0.35, body extent -0.51,-0.25 0.51,0.25, height 0.5
CAPC1005X04L_C2 [mm] "Chip Capacitor, 2-Leads, Body 1.0x0.5mm, IPC High Density"
  rect 0.425x0.5 smd mask+0.05: 1(-0.463,0) 2(0.463,0)
  silkscreen extent -0.77,-0.35 0.77,0.35, body extent -0.51,-0.25 0.51,0.25, height 0.5
CAPC1608X06L [mm] "Chip Capacitor, 2-Leads, Body 1.6x0.8mm, IPC High Density"
  rect 0.75x0.8 smd: 1(-0.675,0) 2(0.675,0)
  silkscreen extent -1.17,-0.5 1.17,0.5, body extent -0.8,-0.43 0.8,0.43, height 0.8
